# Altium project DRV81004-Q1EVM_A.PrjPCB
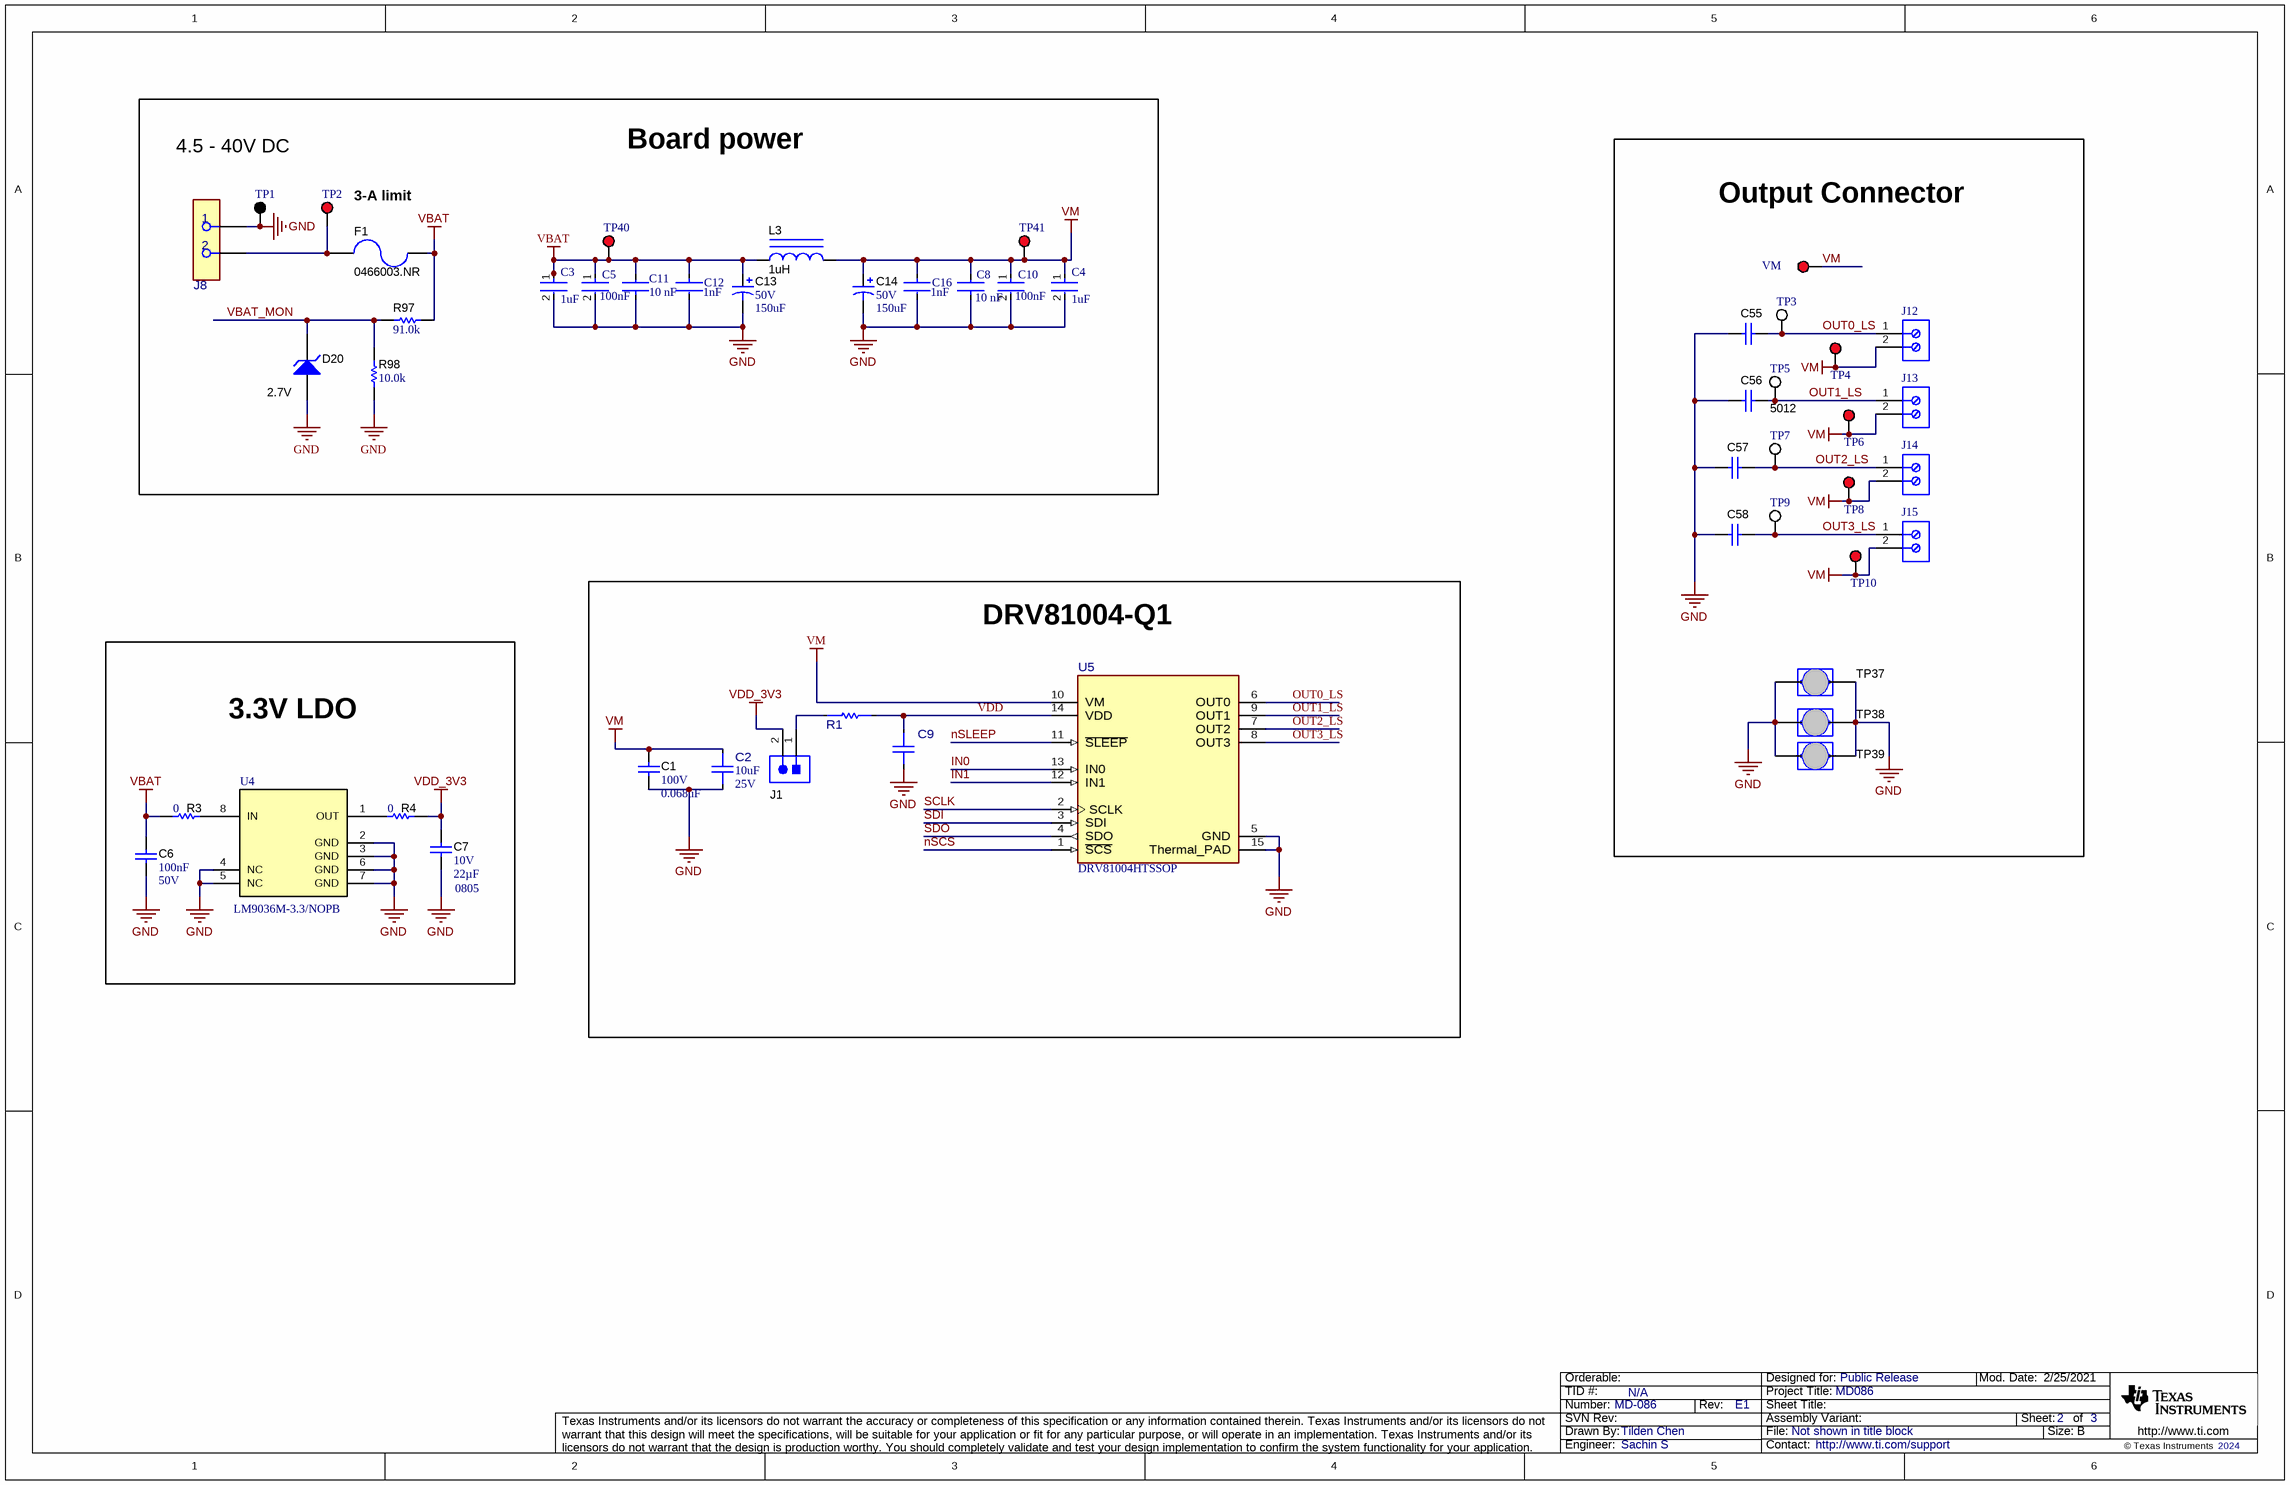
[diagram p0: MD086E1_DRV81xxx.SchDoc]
CopyrightYear: 2024; PCB_Layout: Audrey Kuehler; PCB_Rev: E1; PRJ_Customer: Public Release; PRJ_Engineer: Sachin S; PRJ_Number: MD-086; PRJ_Title: MD086; SCH_Rev: E1; TechSupport: http://www.ti.com/support; TID: N/A
4 sheets, 226 parts. Net scope: global (net labels, ports and power ports of the same name join across sheets).
Board file: DRV81004-Q1EVM_A -051324.PcbDoc
Sheets:
  MD086E1_DRV81xxx.SchDoc
  MD086E1_ezFET.SchDoc
  MD086E1_Hardware.SchDoc
  MD086E1_MCU.SchDoc

## Sheet MD086E1_DRV81xxx.SchDoc
size 431 x 279 mm; Date: Not shown in title block; ApprovedBy: Not shown in title block; CheckedBy: Not shown in title block; Author: Not shown in title block; CompanyName: Not shown in title block; DrawnBy: Tilden Chen; Engineer: Sachin S; Organization: Not shown in title block; Address1: Not shown in title block; Address2: Not shown in title block; Address3: Not shown in title block; Address4: Not shown in title block; DocumentNumber: 2; Revision: Use project parameter SCH_Rev; SheetNumber: 2; SheetTotal: 3; PageSetup: Record=PageOptions¦CenterHorizontal=True¦CenterVertical=True¦PrintScale=1.00¦XCorrection=1.00¦YCorrection=1.00¦PrintKind=0¦BorderSize=5000000¦LeftOffset=0¦BottomOffset=0¦Orientation=2¦PaperLength=1000¦PaperWidth=1000¦Scale=100¦PaperSource=15¦PrintQuality=600¦MediaType=1¦DitherType=10¦PaperKind=Letter¦PrintScaleMode=1

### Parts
C1  VDC_V: 100V  ValueDisplayed: 0.068uF  [1206]  (hidden comment: 12061C683KAT2A)
C2  ValueDisplayed: 10uF  VDC_V: 25V  [FP-ZRB18AR61E106ME01L_0603-MFG]  (hidden comment: ZRB18AR61E106ME01L)
C3  Capacitance: 1uF  [FP-0603-L_1_6_0_15-W_0_8-IPC_C]  (hidden comment: UMK107AB7105KA-T)
C4  Capacitance: 1uF  [FP-0603-L_1_6_0_15-W_0_8-IPC_C]  (hidden comment: UMK107AB7105KA-T)
C5  value 100nF  [FP-885012206095-MFG]  (hidden comment: 885012206095)
C6  Cap_F: 100nF  VDC_V: 50V  [0603]  (hidden comment: 885012206095)
C7  PackageReference: 0805  VDC_V: 10V  ValueDisplayed: 22µF  [0805_150]  (hidden comment: 885012107011)
C8  value 10 nF  [FP-CC0603-DA-MFG]  (hidden comment: CC0603KPX7R9BB103)
C9  885012205018  [FP-885012205018_0402-MFG]  (value not drawn)
C10  value 100nF  [FP-885012206095-MFG]  (hidden comment: 885012206095)
C11  value 10 nF  [FP-CC0603-DA-MFG]  (hidden comment: CC0603KPX7R9BB103)
C12  1nF  [FP-C0603C-CF-MFG]
C13  VDC_V: 50V  ValueDisplayed: 150uF  [SM_RADIAL_G]  (hidden comment: EEE-FK1H151P)
C14  VDC_V: 50V  ValueDisplayed: 150uF  [SM_RADIAL_G]  (hidden comment: EEE-FK1H151P)
C16  1nF  [FP-C0603C-CF-MFG]
C55  885012206114  [0603]  (value not drawn)
C56  885012206114  [0603]  (value not drawn)
C57  885012206114  [0603]  (value not drawn)
C58  885012206114  [0603]  (value not drawn)
D20  value 2.7V  [SOD-123]  (hidden comment: MMSZ4682-E3-08)
F1  0466003.NR  [1206]
J1  HTSW-102-07-G-S  [Samtec_HTSW-102-07-G-S]  (value not drawn)
J8  691250610002  [FP-691250610002_CONN_TERM_BLOCK2-MFG]  (value not drawn)
J12  691101710002  [691101710002]  (value not drawn)
J13  691101710002  [691101710002]  (value not drawn)
J14  691101710002  [691101710002]  (value not drawn)
J15  691101710002  [691101710002]  (value not drawn)
L3  ValueDisplayed: 1uH  [WE-HCC_1210]  (hidden comment: 7443320100)
R1  SG73S1JTTD101J  [FP-SG73S1JTTD101J_0603-MFG]  (value not drawn)
R3  value 0  [0603L]  (hidden comment: Resistor)
R4  value 0  [0603L]  (hidden comment: Resistor)
R97  ValueDisplayed: 91.0k  [0603L]  (hidden comment: RG1608P-913-B-T5)
R98  ValueDisplayed: 10.0k  [0603L]  (hidden comment: RG1608P-103-B-T5)
TP1  5011  [Keystone5011]  (value not drawn)
TP2  5010  [Keystone5010]  (value not drawn)
TP3  5012  [Keystone5012]  (value not drawn)
TP4  5010  [Keystone5010]  (value not drawn)
TP5  5012  [Keystone5012]
TP6  5010  [Keystone5010]  (value not drawn)
TP7  5012  [Keystone5012]  (value not drawn)
TP8  5010  [Keystone5010]  (value not drawn)
TP9  5012  [Keystone5012]  (value not drawn)
TP10  5010  [Keystone5010]  (value not drawn)
TP37  Jumper_2p  [Harwin_D3082-05]  (value not drawn)
TP38  Jumper_2p  [Harwin_D3082-05]  (value not drawn)
TP39  Jumper_2p  [Harwin_D3082-05]  (value not drawn)
TP40  5010  [Keystone5010]  (value not drawn)
TP41  5010  [Keystone5010]  (value not drawn)
U4  LM9036M-3.3/NOPB  [D0008A_N]
U5  DRV81004HTSSOP  [PWP0014L-MFG]
VM  5010  [Keystone5010]  (value not drawn)

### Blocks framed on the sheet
Board power: C3-C5 C8 C10-C14 C16 D20 F1 J8 L3 R97 R98 TP1 TP2 TP40 TP41
Output Connector: C55-C58 J12-J15 TP3-TP10 TP37-TP39 VM
DRV81004-Q1: C1 C2 C9 J1 R1 U5
3.3V LDO: C6 C7 R3 R4 U4

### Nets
GND: C1.2 C2.2 C3.2 C4.2 C5.2 C6.2 C7.2 C8.1 C9.2 C10.2 C11.1 C12.2 C13.2(-) C14.2(-) C16.2 C55.2 C56.2 C57.2 C58.2 D20.2(A) J8.1 R98.1 TP1.1 TP37.1 TP37.2 TP38.1 TP38.2 TP39.1 TP39.2 U4.2(GND) U4.3(GND) U4.4(NC) U4.5(NC) U4.6(GND) U4.7(GND) U5.5(GND) U5.15(Thermal_PAD)
VBAT: C3.1 C5.1 C6.1 C11.2 C12.1 C13.1(+) F1.1 L3.1 R3.2 R97.2 TP40.1  [project net VS]
VDD_3V3: C7.1 J1.2 R4.1
VM: C1.1 C2.1 C4.1 C8.2 C10.1 C14.1(+) C16.1 J12.2 J13.2 J14.2 J15.2 L3.2 TP4.1 TP6.1 TP8.1 TP10.1 TP41.1 U5.10(VM) VM.1
IN0: U5.13(IN0)
IN1: U5.12(IN1)
nSCS: U5.1(~{SCS})
nSLEEP: U5.11(~{SLEEP})
OUT0_LS: C55.1 J12.1 TP3.1 U5.6(OUT0)
OUT1_LS: C56.1 J13.1 TP5.1 U5.9(OUT1)
OUT2_LS: C57.1 J14.1 TP7.1 U5.7(OUT2)
OUT3_LS: C58.1 J15.1 TP9.1 U5.8(OUT3)
SCLK: U5.2(SCLK)
SDI: U5.3(SDI)
SDO: U5.4(SDO)
VBAT_MON: D20.1(K) R97.1 R98.2
VDD: C9.1 R1.2 U5.14(VDD)
NetF1_2: F1.2 J8.2 TP2.1
NetJ1_1: J1.1 R1.1
NetR3_1: R3.1 U4.8(IN)
NetR4_2: R4.2 U4.1(OUT)

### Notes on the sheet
- 4.5 - 40V DC
- 3-A limit

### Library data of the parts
C1 = CMP-0008507-2: CAP, CERM, 0.068 uF, 100 V, +/- 10%, X7R, 1206; Manufacturer: AVX; TaMin_C: -55°C; ESR_ohm: 0.045; Polarized: N; SizeAreaWB_mm2: 10.92; Value1: 0.045 ohm; U/M: EA; TaMax_C: 125°C; SizeZ_mm: 1.35; SizeX_mm: 3.2; SizeY_mm: 1.6; SizeArea_mm2: 5.12; Cap_F: 68nF; AEC Category: Q200
C2 = CMP-0094458-1: 10µF ±20% 25V Ceramic Capacitor X5R 0603 (1608 Metric); Manufacturer: Murata Electronics; SizeZ_mm: 1.2mm; AEC Qualified: No
C3 C4 = CMP-2000-07531-4: Ceramic Capacitor General Use 1uF ±10% 50V X7R 0603
C5 C10 = CMP-207839-000004-1: CAP CER 0.1UF 50V X7R 0603; Tolerance: 10%
C6 = CMP-0006837-4: CAP, CERM, 0.1 uF, 50 V, +/- 10%, X7R, 0603; Manufacturer: Wurth Elektronik; TaMin_C: -55°C; Polarized: N; SizeAreaWB_mm2: 4.68; Value1: Unknown; U/M: EA; Value: 0.1uF; TaMax_C: 125°C; SizeZ_mm: 1; SizeX_mm: 1.6; SizeY_mm: 0.8; SizeArea_mm2: 1.28; AEC Category: Q200
C7 = CMP-0078153-1: CAP, CERM, 22 µF, 10 V,+/- 20%, X5R, 0805; Manufacturer: Wurth Elektronik; TaMin_C: -55°C; Polarized: N; SizeAreaWB_mm2: 6.75; U/M: EA; Value: 22uF; TaMax_C: 85°C; SizeZ_mm: 1.5; SizeX_mm: 2; SizeY_mm: 1.25; SizeArea_mm2: 2.5; AEC Category: Q200
C8 C11 = CMP-1035-02321-3: CAP CER 10000PF 50V X7R 0603; Manufacturer: YAGEO; Alternative PartNumber: 885382206002; Alternative Manufacturer: Wurth Elektronik; Tolerance: 0.1; Material: Ceramic; Temperature Coefficient: 15%
C9 = CMP-0090362-1: 0.1µF ±10% 10V Ceramic Capacitor X7R 0402 (1005 Metric); Manufacturer: Wurth Electronics; AEC Qualified: No; Value: 100nF; SizeZ_mm: 0.55mm; ValueDisplayed: 100000pF; TempCo: 15%
C12 C16 = CMP-03020-030804-1: CAP CER 1000PF 50V X7R 0603; Manufacturer Part Number: C0603C102J5RACAUTO; Manufacturer: KEMET; Alternate PartNumber: 885012206083; Alternate Manufacturer: Wurth Elektronik; Material: Ceramic; Value: 1,000 pF; Temperature Coefficient: 30ppm/°C; Automotive Grade: Grade 1; Tolerance: 0.05
C13 C14 = CMP-0011178-2: CAP, AL, 150 uF, 50 V, +/- 20%, 0.18 ohm, AEC-Q200 Grade 2, SMD; Manufacturer: Panasonic; Alternate Manufacturer: Wurth Elektronik; Alternate PartNumber: 865080657017; TaMin_C: -55°C; ESR_ohm: 0.18; Polarized: Y; SizeAreaWB_mm2: 172.2; U/M: EA; Value: 150uF; TaMax_C: 105°C; SizeZ_mm: 10.2; SizeX_mm: 12; SizeY_mm: 10.3; Cap_Case: G; SizeArea_mm2: 123.6; CompType: Capacitor; Cap_F: 150µF; IRMS_A: 670mA; AEC Grade: 2; AEC Category: Q200
C55-C58 = CMP-0079993-1: CAP, CERM, 0.01 µF, 100 V,+/- 10%, X7R, 0603; Manufacturer: Wurth Elektronik; TaMin_C: -55°C; Polarized: N; SizeAreaWB_mm2: 4.68; U/M: EA; Value: 0.01uF; TaMax_C: 105°C; SizeZ_mm: 1; SizeX_mm: 1.6; SizeY_mm: 0.8; Value2: 100V; SizeArea_mm2: 1.28; Cap_F: 10nF; AEC Category: Q200; ValueDisplayed: 0.01µF
D20 = CMP-0077592-3: Diode, Zener, 2.7 V, 500 mW, SOD-123; Manufacturer: Vishay-Semiconductor; AEC Category: Q101; AEC Qualified: N; SizeAreaWB_mm2: 13.095; SizeY_mm: 1.7; SizeX_mm: 3.85; Value1: 0.5W; SizeArea_mm2: 6.545; SizeZ_mm: 1.35; RJA_CperW: 340; Power_W: 500mW
F1 = CMP-0084439-1: Fuse, 3 A, 32VAC/VDC, SMD; Manufacturer: Littelfuse; VAC_V: 32V; Rtyp_Ohm: 0.019; Interrupt_AC: 50A; MeltingTyp: 0.576; SizeX_mm: 3.2; Fuse Technology: Board Mount; Irating_A: 3A; SizeAreaWB_mm2: 10.92; TaMin_C: -55°C; Fuse Speed: Fast; SizeArea_mm2: 5.12; SizeY_mm: 1.6; SizeZ_mm: 1.35; TaMax_C: 90°C
J1 = CMP-0075483-1: Header, 100mil, 2x1, Gold, TH; Manufacturer: Samtec; Green_REACh: Passed; CT: False; Green_Lifecycle: Active; CNHeader: True
J8 = CMP-0093233-2: 2 Position Wire to Board Terminal Block Horizontal with Board 0.250" (6.35mm) Through Hole; Manufacturer: Wurth Electronics; Current_A: 32A; Conn Gender: Female; Row_Count: 1; ContactFinish: Zinc; SizeZ_mm: 21.6mm; Max Wire Gauge: 10; Min Wire Gauge: 30; Voltage_V: 450V; AEC Qualified: No; Is Female: yes
J12-J15 = CMP-1502-03256-1: Series 101 - 5.00 mm Horizontal Entry Modular with Pressure Clamp WR-TBL, 2 pin; Manufacturer: Wurth Elektronik; Pin Number: 2; Pitch: 5.00mm
L3 = CMP-0063986-1: Inductor, Shielded Drum Core, Ferrite, 1 uH, 24 A, 0.0012 ohm, SMD; Manufacturer: Wurth Elektronik; Isat: 32A @ 30% inductance drop; Irms: 24A @ 50C rise; Green_Lifecycle: Active; SizeAreaWB_mm2: 188.94; DCR_ohm: 1.2m; Green_REACh: Passed; Value: 1uH; Imax_A: 24A; SizeZ_mm: 10; SizeX_mm: 12.1; SizeY_mm: 11.4; SizeArea_mm2: 137.94; Ind_H: 1µH; AEC Category: Q200
R1 = CMP-0095262-1: 100 Ohms ±5% 0.2W, 1/5W Chip Resistor 0603 (1608 Metric) Automotive AEC-Q200, Moisture Resistant, Pulse Withstanding Thick Film; Manufacturer: KOA Speer; AEC Qualified: Yes; Value: 100; AEC Grade: Grade 0; VDC_V: 150V; TaMax_C: +70°C; TempCo: 100ppm/°C; Power_W: 200mW; SizeZ_mm: 0.55mm
R3 R4 = CMP-0025697-4: RES, 0, 5%, 0.1 W, AEC-Q200 Grade 0, 0603; PartNumber: CRCW06030000Z0EA; Manufacturer: Vishay-Dale; Value_Code: 0000; Power_W: 100mW; Value2: 0.1W; VDC_V: 75V; TempCo: 200 ppm/C; EIA_Code: E24; AEC Category: Q200; AEC Qualified: Y; SizeArea_mm2: 1.28; SizeX_mm: 1.6; SizeY_mm: 0.8; SizeZ_mm: 1
R97 = CMP-0023620-3: RES, 91.0 k, 0.1%, 0.1 W, 0603; Manufacturer: Susumu Co Ltd; Power_W: 100mW; TempCo: 25 ppm/C; Value_Code: 91k0; U/M: EA; Value: 91.0k; Res_ohm: 91k; SizeX_mm: 1.6; SizeY_mm: 0.8; SizeZ_mm: 1; Value2: 0.1W; SizeArea_mm2: 1.28; VDC_V: 75V; AEC Category: Q200
R98 = CMP-0023404-3: RES, 10.0 k, 0.1%, 0.1 W, 0603; Manufacturer: Susumu Co Ltd; Power_W: 100mW; TempCo: 25 ppm/C; Value_Code: 10k0; U/M: EA; Value: 10.0k; EIA_Code: E192; Res_ohm: 10k; SizeX_mm: 1.6; SizeY_mm: 0.8; SizeZ_mm: 1; Value2: 0.1W; SizeArea_mm2: 1.28; VDC_V: 75V; AEC Category: Q200
TP1 = CMP-0055148-2: Test Point, Multipurpose, Black, TH; Manufacturer: Keystone Electronics; CNHeader: FALSE; Green_Lifecycle: Active; Green_REACh: Passed; ContactFinish: Silver; CT: TRUE
TP2 TP4 TP6 TP8 TP10 VM = CMP-0055147-2: Test Point, Multipurpose, Red, TH; Manufacturer: Keystone Electronics; CNHeader: FALSE; Green_Lifecycle: Active; Green_REACh: Passed; ContactFinish: Silver; CT: TRUE
TP3 TP5 TP7 TP9 = CMP-0055149-2: Test Point, Multipurpose, White, TH; Manufacturer: Keystone Electronics; ContactFinish: Silver; CT: TRUE; CNHeader: FALSE; Green_Lifecycle: Active; Green_REACh: Passed
TP37-TP39 = CMP-0075110-1: 1mm Uninsulated Shorting Plug, 10.16mm spacing, TH; Manufacturer: Harwin; PartNumber: D3082-05; CompType: Jumper Wire; CNHeader: False; Green_Lifecycle: Active; Green_REACh: Passed
TP40 TP41 = CMP-0055147-1: Test Point, Multipurpose, Red, TH; Manufacturer: Keystone; CNHeader: FALSE; Green_Lifecycle: Active; Green_REACh: Passed; ContactFinish: Silver; CT: TRUE
U4 = CMP-0070570-1: Ultra-Low Quiescent Current Voltage Regulator, 8-pin Narrow SOIC, Pb-Free; Manufacturer: Texas Instruments; PackageTopMarking: NSZXTT*LM903*6M-3; PowerWise: N; CompType: LDO IC
U5 = CMP-0120416-1: 4-channel Low-side Driver for Automotive Relay Control; Manufacturer: Texas Instruments; SizeZ_mm: 1.2mm; AEC Qualified: No; Max Supply Voltage: 40V; Min Supply Voltage: 3V; Number Of Outputs: 4; Standoff Height: 0.05mm; TaMax_C: +125°C; TaMin_C: -40°C; TJmax_C: +150°C

## Sheet MD086E1_ezFET.SchDoc
size 431 x 279 mm; Date: Not shown in title block; ApprovedBy: Not shown in title block; CheckedBy: Not shown in title block; Author: Not shown in title block; CompanyName: Not shown in title block; DrawnBy: Murugavel Raju; Engineer: Sachin S; Organization: Not shown in title block; Address1: Not shown in title block; Address2: Not shown in title block; Address3: Not shown in title block; Address4: Not shown in title block; DocumentNumber: 1; Revision: Use project parameter SCH_Rev; SheetNumber: 1; SheetTotal: 3; PageSetup: Record=PageOptions¦CenterHorizontal=True¦CenterVertical=True¦PrintScale=1.00¦XCorrection=1.00¦YCorrection=1.00¦PrintKind=0¦BorderSize=5000000¦LeftOffset=0¦BottomOffset=0¦Orientation=2¦PaperLength=1000¦PaperWidth=1000¦Scale=100¦PaperSource=15¦PrintQuality=600¦MediaType=1¦DitherType=10¦PaperKind=Letter¦PrintScaleMode=1
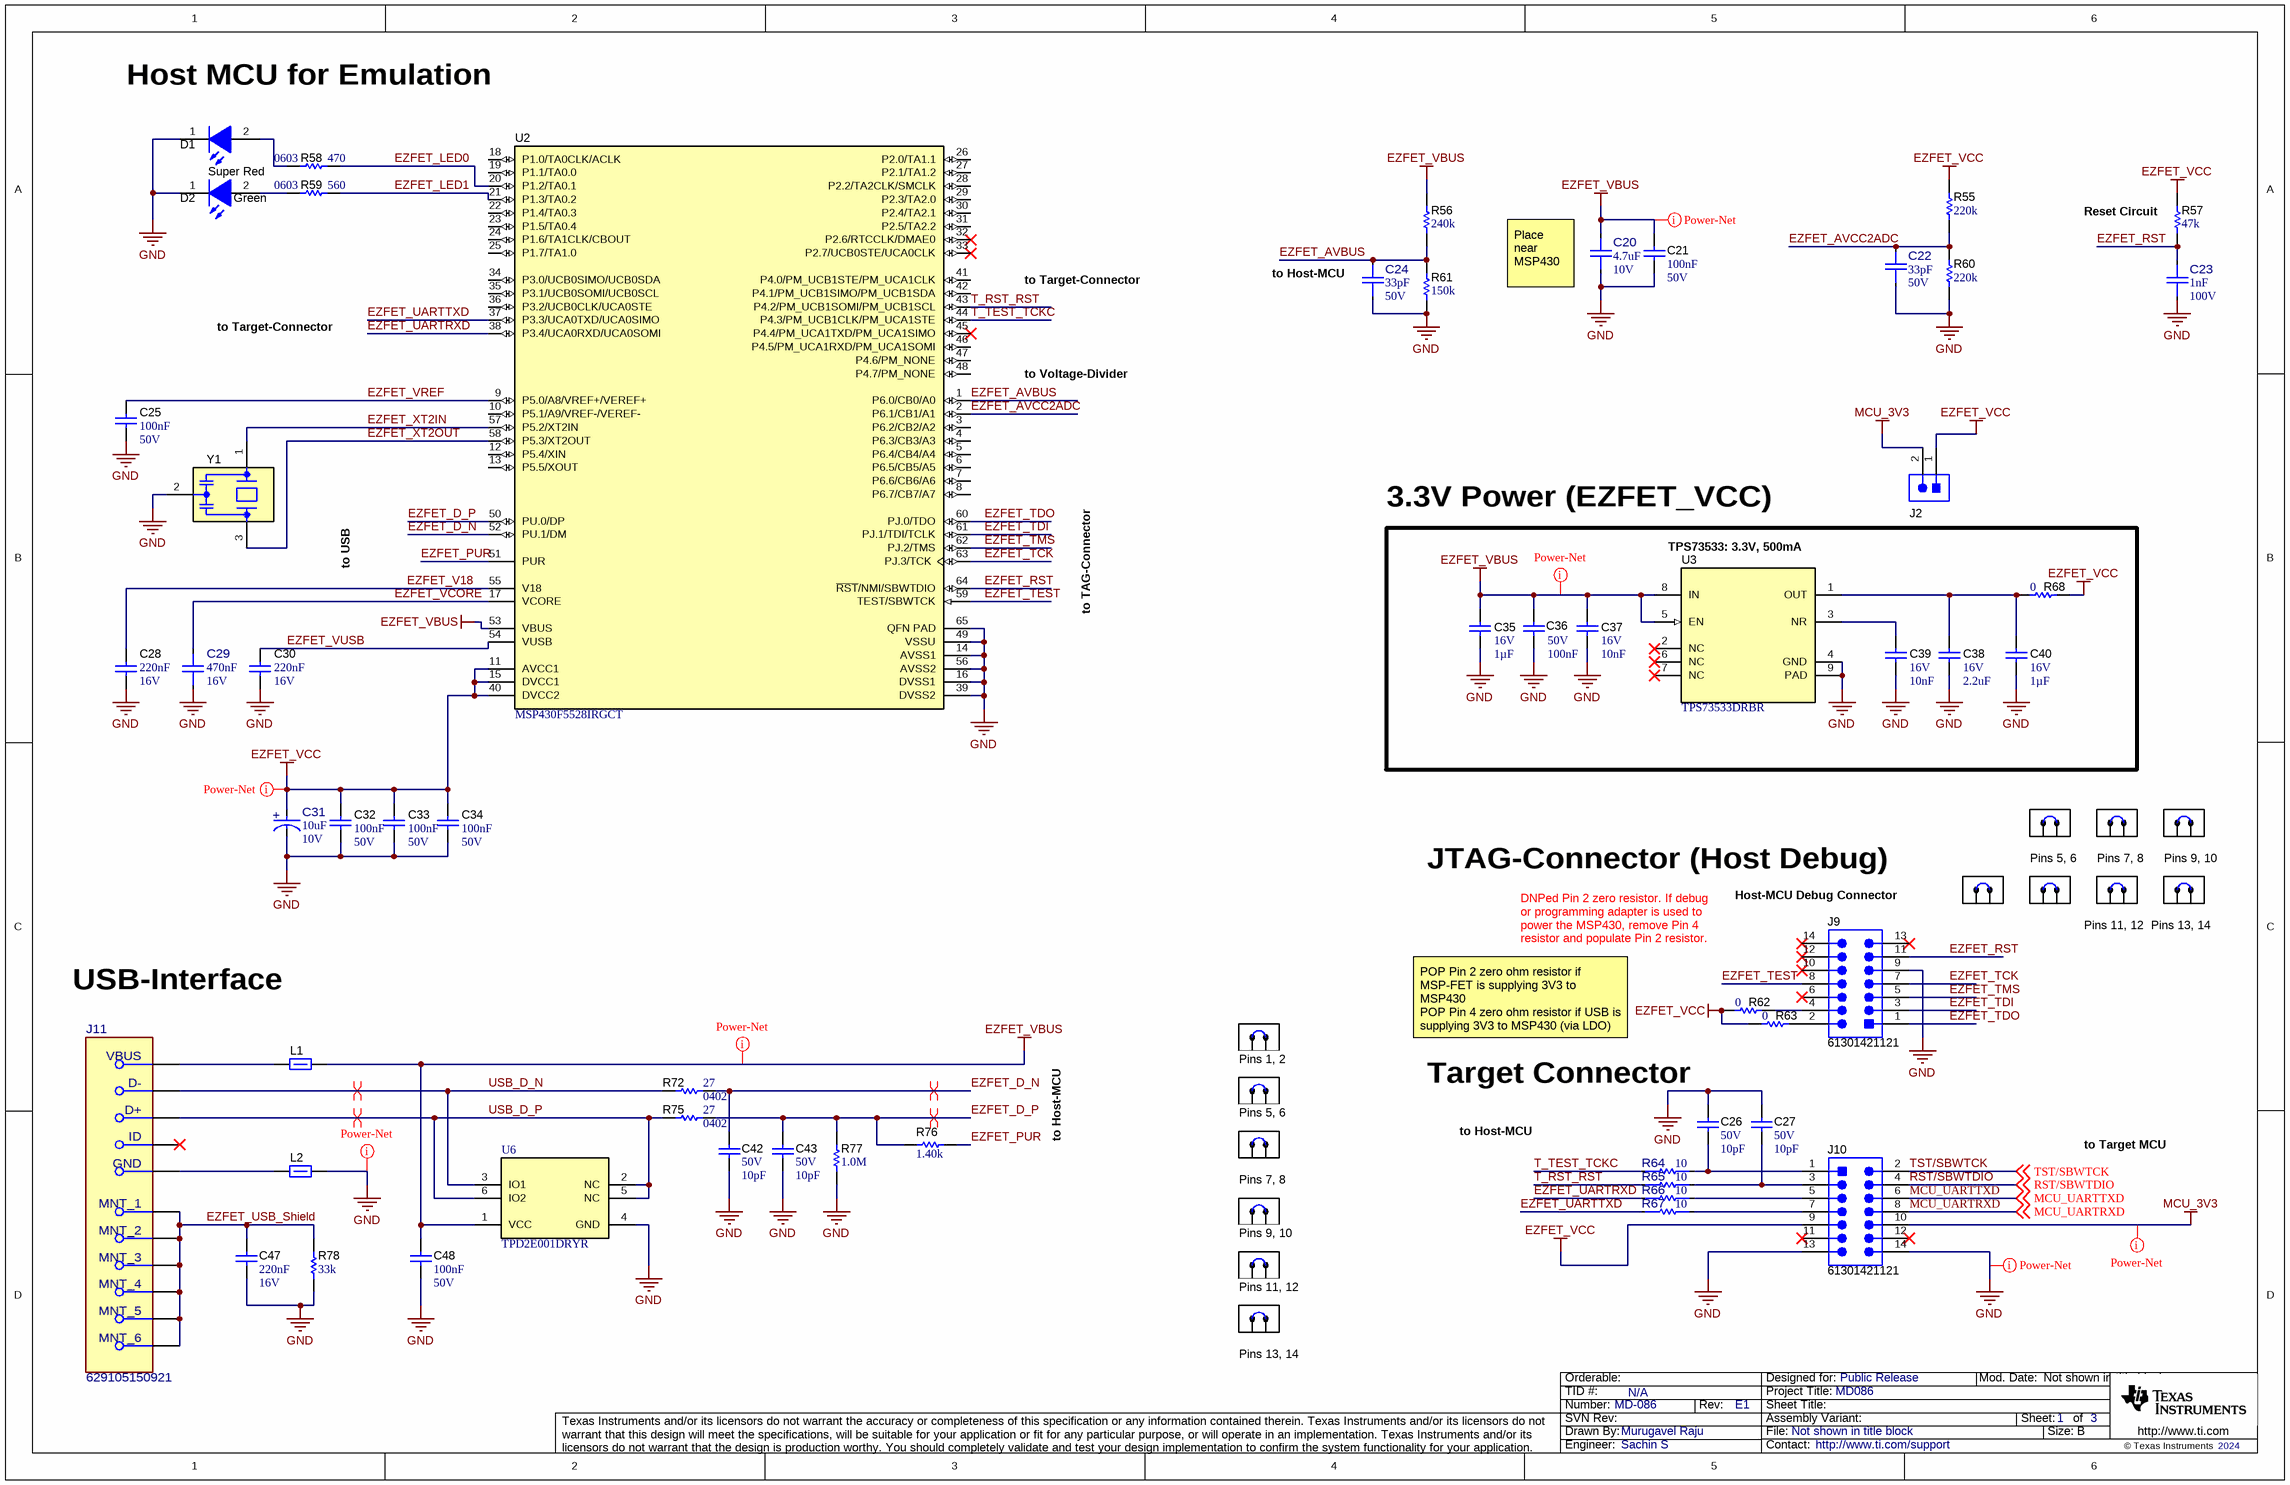
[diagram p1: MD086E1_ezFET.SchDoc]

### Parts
C20  ValueDisplayed: 4.7uF  VDC_V: 10V  [FP-885012106012_0603-MFG]  (hidden comment: 885012106012)
C21  Cap_F: 100nF  VDC_V: 50V  [0603]  (hidden comment: 885012206095)
C22  ValueDisplayed: 33pF  VDC_V: 50V  [FP-885012005058_0402-MFG]  (hidden comment: 885012005058)
C23  ValueDisplayed: 1nF  VDC_V: 100V  [FP-885012006085_0603-MFG]  (hidden comment: 885012006085)
C24  ValueDisplayed: 33pF  VDC_V: 50V  [FP-885012005058_0402-MFG]  (hidden comment: 885012005058)
C25  Cap_F: 100nF  VDC_V: 50V  [0603]  (hidden comment: 885012206095)
C26  VDC_V: 50V  ValueDisplayed: 10pF  [0402]  (hidden comment: 885012005055)
C27  VDC_V: 50V  ValueDisplayed: 10pF  [0402]  (hidden comment: 885012005055)
C28  Cap_F: 220nF  VDC_V: 16V  [0603L]  (hidden comment: 885012206048)
C29  VDC_V: 16V  Cap_F: 470nF  [FP-885012206050_0603-MFG]  (hidden comment: 885012206050)
C30  Cap_F: 220nF  VDC_V: 16V  [0603L]  (hidden comment: 885012206048)
C31  ValueDisplayed: 10uF  VDC_V: 10V  [FP-875105240001_SMT_CAP_4MM3_4MM3-MFG]  (hidden comment: 875105240001)
C32  Cap_F: 100nF  VDC_V: 50V  [0603]  (hidden comment: 885012206095)
C33  Cap_F: 100nF  VDC_V: 50V  [0603]  (hidden comment: 885012206095)
C34  Cap_F: 100nF  VDC_V: 50V  [0603]  (hidden comment: 885012206095)
C35  Cap_F: 1µF  VDC_V: 16V  [0603]  (hidden comment: 885012206052)
C36  Cap_F: 100nF  VDC_V: 50V  [0603]  (hidden comment: 885012206095)
C37  Cap_F: 10nF  VDC_V: 16V  [0603]  (hidden comment: 885012206040)
C38  VDC_V: 16V  ValueDisplayed: 2.2uF  [0603]  (hidden comment: 885012106018)
C39  Cap_F: 10nF  VDC_V: 16V  [0603]  (hidden comment: 885012206040)
C40  Cap_F: 1µF  VDC_V: 16V  [0603]  (hidden comment: 885012206052)
C42  VDC_V: 50V  ValueDisplayed: 10pF  [0402]  (hidden comment: 885012005055)
C43  VDC_V: 50V  ValueDisplayed: 10pF  [0402]  (hidden comment: 885012005055)
C47  Cap_F: 220nF  VDC_V: 16V  [0603L]  (hidden comment: 885012206048)
C48  Cap_F: 100nF  VDC_V: 50V  [0603]  (hidden comment: 885012206095)
D1  value Super Red  [WL-SMCW_RED]  (hidden comment: 150060SS75000)
D2  value Green  [WL-SMCW_GREEN]  (hidden comment: 150060VS75000)
J2  HTSW-102-07-G-S  [Samtec_HTSW-102-07-G-S]  (value not drawn)
J9  61301421121  [Wurth_61301421121]
J10  61301421121  [Wurth_61301421121]
J11  629105150921  [FP-629105150921_CONN_PTH_USB_8MM0_5MM6-MFG]
L1  742792621  [0603L]  (value not drawn)
L2  742792621  [0603L]  (value not drawn)
R55  ValueDisplayed: 220k  [0402]  (hidden comment: RC0402FR-07220KL)
R56  ValueDisplayed: 240k  [0402]  (hidden comment: CRCW0402240KFKED)
R57  ValueDisplayed: 47k  [0402]  (hidden comment: CRCW040247K0JNED)
R58  ValueDisplayed: 470  [0603]  (hidden comment: RC0603JR-07470RL)
R59  ValueDisplayed: 560  [0603]  (hidden comment: RC0603JR-07560RL)
R60  ValueDisplayed: 220k  [0402]  (hidden comment: RC0402FR-07220KL)
R61  ValueDisplayed: 150k  [0402]  (hidden comment: CRCW0402150KFKED)
R62  value 0  [0603L]  (hidden comment: Resistor)
R63  value 0  [0603L]  (hidden comment: Resistor)
R64  value 10  [FP-560050310009_0402-MFG]  (hidden comment: 560050310009)
R65  value 10  [FP-560050310009_0402-MFG]  (hidden comment: 560050310009)
R66  value 10  [FP-560050310009_0402-MFG]  (hidden comment: 560050310009)
R67  value 10  [FP-560050310009_0402-MFG]  (hidden comment: 560050310009)
R68  value 0  [0603L]  (hidden comment: Resistor)
R72  PackageReference: 0402  ValueDisplayed: 27  [0402L]  (hidden comment: CRCW040227R0JNED)
R75  PackageReference: 0402  ValueDisplayed: 27  [0402L]  (hidden comment: CRCW040227R0JNED)
R76  ValueDisplayed: 1.40k  [0402L]  (hidden comment: CRCW04021K40FKED)
R77  ValueDisplayed: 1.0M  [0402L]  (hidden comment: CRCW04021M00JNED)
R78  ValueDisplayed: 33k  [0402S]  (hidden comment: CRCW040233K0JNED)
SH-J22  60900213421  [Wurth_60900213421]  (value not drawn)
SH-J23  60900213421  [Wurth_60900213421]  (value not drawn)
SH-J24  60900213421  [Wurth_60900213421]  (value not drawn)
SH-J25  60900213421  [Wurth_60900213421]  (value not drawn)
SH-J26  60900213421  [Wurth_60900213421]  (value not drawn)
SH-J27  60900213421  [Wurth_60900213421]  (value not drawn)
SH-J28  60900213421  [Wurth_60900213421]  (value not drawn)
SH-J29  60900213421  [Wurth_60900213421]  (value not drawn)
SH-J31  60900213421  [Wurth_60900213421]  (value not drawn)
SH-J32  60900213421  [Wurth_60900213421]  (value not drawn)
SH-J33  60900213421  [Wurth_60900213421]  (value not drawn)
SH-J34  60900213421  [Wurth_60900213421]  (value not drawn)
SH-J35  60900213421  [Wurth_60900213421]  (value not drawn)
U2  MSP430F5528IRGCT  [RGC0064B]
U3  TPS73533DRBR  [DRB0008A]
U6  TPD2E001DRYR  [DRY0006A]
Y1  CSTNR4M00GH5L000R0  [MuRata_CSTNR]  (value not drawn)

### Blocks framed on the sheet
3.3V Power (EZFET_VCC): C35-C40 R68 U3

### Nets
EZFET_VBUS: C20.2 C21.1 C35.1 C36.1 C37.1 C48.2 L1.2 R56.2 U2.53(VBUS) U3.5(EN) U3.8(IN) U6.1(VCC)
EZFET_VCC: C31.2(ANODE) C32.1 C33.1 C34.1 J2.1 J10.9 R55.2 R57.2 R62.2 R63.2 R68.1 U2.11(AVCC1) U2.15(DVCC1) U2.40(DVCC2)
GND: C20.1 C21.2 C22.1 C23.1 C24.1 C25.2 C26.1 C27.1 C28.2 C29.1 C30.2 C31.1(CATHODE) C32.2 C33.2 C34.2 C35.2 C36.2 C37.2 C38.2 C39.2 C40.2 C42.2 C43.2 C47.2 C48.1 D1.1(K) D2.1(K) J9.9 J10.13 J10.14 L2.2 R60.1 R61.1 R77.1 R78.1 U2.14(AVSS1) U2.16(DVSS1) U2.39(DVSS2) U2.49(VSSU) U2.56(AVSS2) U2.65(QFN_PAD) U3.4(GND) U3.9(PAD) U6.4(GND) Y1.2(GND)
MCU_3V3: J2.2 J10.10
EZFET_AVBUS: C24.2 R56.1 R61.2 U2.1(P6.0/CB0/A0)
EZFET_AVCC2ADC: C22.2 R55.1 R60.2 U2.2(P6.1/CB1/A1)
EZFET_D_N: C42.1 R72.2 U2.52(PU.1/DM)
EZFET_D_P: C43.1 R75.2 R76.1 R77.2 U2.50(PU.0/DP)
EZFET_LED0: R58.1 U2.20(P1.2/TA0.1)
EZFET_LED1: R59.1 U2.21(P1.3/TA0.2)
EZFET_PUR: R76.2 U2.51(PUR)
EZFET_RST: C23.2 J9.11 R57.1 U2.64(~{RST}/NMI/SBWTDIO)
EZFET_TCK: J9.7 U2.63(PJ.3/TCK)
EZFET_TDI: J9.3 U2.61(PJ.1/TDI/TCLK)
EZFET_TDO: J9.1 U2.60(PJ.0/TDO)
EZFET_TEST: J9.8 U2.59(TEST/SBWTCK)
EZFET_TMS: J9.5 U2.62(PJ.2/TMS)
EZFET_UARTRXD: R66.1 U2.38(P3.4/UCA0RXD/UCA0SOMI)
EZFET_UARTTXD: R67.1 U2.37(P3.3/UCA0TXD/UCA0SIMO)
EZFET_USB_Shield: C47.1 J11.6(MNT_1) J11.7(MNT_2) J11.8(MNT_3) J11.9(MNT_4) J11.10(MNT_5) J11.11(MNT_6) R78.2
EZFET_V18: C28.1 U2.55(V18)
EZFET_VCORE: C29.2 U2.17(VCORE)
EZFET_VREF: C25.1 U2.9(P5.0/A8/VREF+/VEREF+)
EZFET_VUSB: C30.1 U2.54(VUSB)
EZFET_XT2IN: U2.57(P5.2/XT2IN) Y1.1(In)
EZFET_XT2OUT: U2.58(P5.3/XT2OUT) Y1.3(Out)
MCU_UARTRXD: J10.8 ; off-sheet MCU_UARTRXD
MCU_UARTTXD: J10.6 ; off-sheet MCU_UARTTXD
RST/SBWTDIO: J10.4 ; off-sheet RST/SBWTDIO
T_RST_RST: R65.1 U2.43(P4.2/PM_UCB1SOMI/PM_UCB1SCL)
T_TEST_TCKC: R64.1 U2.44(P4.3/PM_UCB1CLK/PM_UCA1STE)
TST/SBWTCK: J10.2 ; off-sheet TST/SBWTCK
USB_D_N: J11.2(D-) R72.1 U6.3(IO1)
USB_D_P: J11.3(D+) R75.1 U6.2(NC) U6.5(NC) U6.6(IO2)
NetC26_2: C26.2 J10.1 R64.2
NetC27_2: C27.2 J10.3 R65.2
NetC38_1: C38.1 C40.1 R68.2 U3.1(OUT)
NetC39_1: C39.1 U3.3(NR)
NetD1_2: D1.2(A) R58.2
NetD2_2: D2.2(A) R59.2
NetJ9_2: J9.2 R63.1
NetJ9_4: J9.4 R62.1
NetJ10_5: J10.5 R66.2
NetJ10_7: J10.7 R67.2
NetJ11_1: J11.1(VBUS) L1.1
NetJ11_5: J11.5(GND) L2.1

Not connected (* = marked no-connect by the designer): J9 6* 10* 12* 13* 14*; J10 11* 12*; J11 4(ID)*; U2 3(P6.2/CB2/A2) 4(P6.3/CB3/A3) 5(P6.4/CB4/A4) 6(P6.5/CB5/A5) 7(P6.6/CB6/A6) 8(P6.7/CB7/A7) 10(P5.1/A9/VREF-/VEREF-) 12(P5.4/XIN) 13(P5.5/XOUT) 18(P1.0/TA0CLK/ACLK) 19(P1.1/TA0.0) 22(P1.4/TA0.3) 23(P1.5/TA0.4) 24(P1.6/TA1CLK/CBOUT) 25(P1.7/TA1.0) 26(P2.0/TA1.1) 27(P2.1/TA1.2) 28(P2.2/TA2CLK/SMCLK) 29(P2.3/TA2.0) 30(P2.4/TA2.1) 31(P2.5/TA2.2) 32(P2.6/RTCCLK/DMAE0)* 33(P2.7/UCB0STE/UCA0CLK)* 34(P3.0/UCB0SIMO/UCB0SDA) 35(P3.1/UCB0SOMI/UCB0SCL) 36(P3.2/UCB0CLK/UCA0STE) 41(P4.0/PM_UCB1STE/PM_UCA1CLK) 42(P4.1/PM_UCB1SIMO/PM_UCB1SDA) 45(P4.4/PM_UCA1TXD/PM_UCA1SIMO)* 46(P4.5/PM_UCA1RXD/PM_UCA1SOMI) 47(P4.6/PM_NONE) 48(P4.7/PM_NONE); U3 2(NC)* 6(NC)* 7(NC)*

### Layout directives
net class Power-Net: EZFET_VBUS, EZFET_VCC, GND, MCU_3V3
differential pair: EZFET_D_N, EZFET_D_P, USB_D_N, USB_D_P

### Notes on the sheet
- Host MCU for Emulation
- (near R57) Reset Circuit
- to Target-Connector
- (near C24) to Host-MCU
- (near C20) Place near MSP430
- to Voltage-Divider
- to USB
- to TAG-Connector
- (near U3) TPS73533: 3.3V, 500mA
- JTAG-Connector (Host Debug)
- (near J9) Host-MCU Debug Connector
- (near SH-J23) Pins 5, 6
- (near SH-J27) Pins 7, 8
- (near SH-J28) Pins 9, 10
- DNPed Pin 2 zero resistor. If debug or programming adapter is used to power the MSP430, remove Pin 4 resistor and populate Pin 2 resistor.
- Pins 11, 12
- Pins 13, 14
- USB-Interface
- POP Pin 2 zero ohm resistor if MSP-FET is supplying 3V3 to MSP430
  POP Pin 4 zero ohm resistor if USB is supplying 3V3 to MSP430 (via LDO)
- to Host-MCU
- (near SH-J29) Pins 1, 2
- Target Connector
- (near SH-J31) Pins 5, 6
- to Target MCU
- Pins 7, 8
- (near SH-J33) Pins 9, 10
- (near SH-J34) Pins 11, 12
- (near SH-J35) Pins 13, 14

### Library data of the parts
C20 = CMP-0097305-1: 4.7 µF ±20% 10V Ceramic Capacitor X5R 0603 (1608 Metric); Manufacturer: Wurth Electronics; Cap_F: 4.7µF; Value: 4.7µF; AEC Qualified: No; SizeZ_mm: 0.87mm; TempCo: 15%
C21 C25 C32-C34 C36 C48 = CMP-0006837-4: as C6 on sheet MD086E1_DRV81xxx
C22 C24 = CMP-0097306-1: 33 pF ±5% 50V Ceramic Capacitor C0G, NP0 0402 (1005 Metric); Manufacturer: Wurth Electronics; AEC Qualified: No; Value: 33pF; TempCo: 30ppm/°C; SizeZ_mm: 0.55mm
C23 = CMP-0097311-1: 1000 pF ±5% 100V Ceramic Capacitor C0G, NP0 0603 (1608 Metric); Manufacturer: Wurth Electronics; TempCo: 30ppm/°C; SizeZ_mm: 0.87mm; AEC Qualified: No; Value: 1nF
C26 C27 C42 C43 = CMP-0006215-2: CAP, CERM, 10 pF, 50 V, +/- 5%, C0G/NP0, 0402; Manufacturer: Wurth Elektronik; TaMin_C: -55°C; Polarized: N; SizeAreaWB_mm2: 3; Value1: Unknown; U/M: EA; Value: 10pF; TaMax_C: 125°C; SizeZ_mm: 0.6; SizeX_mm: 1; SizeY_mm: 0.5; AEC Category: Q200
C28 C30 C47 = CMP-0006830-4: CAP, CERM, 0.22 uF, 16 V, +/- 10%, X7R, 0603; Manufacturer: Wurth Elektronik; TaMin_C: -55°C; Polarized: N; SizeAreaWB_mm2: 4.68; Value1: Unknown; U/M: EA; Value: 0.22uF; TaMax_C: 125°C; SizeZ_mm: 1; SizeX_mm: 1.6; SizeY_mm: 0.8; Cap_Case: 0603; SizeArea_mm2: 1.28; AEC Category: Q200
C29 = CMP-0097608-1: 0.47 µF ±10% 16V Ceramic Capacitor X7R 0603 (1608 Metric); Manufacturer: Wurth Electronics; AEC Qualified: No; Value: 470nF; TempCo: 15%; SizeZ_mm: 0.87mm
C31 = CMP-0097340-1: Alum. Polymer Cap 10µF 10V 5.5mmV-Chip WCAP-PSLP Series Lifetime 2000h +105°C; Manufacturer: Wurth Electronics; Life: 2000Hours; Dissipation Factor: 8%; Esr: 45m; IRMS_A: 1.2A; Tolerance_%: 20%; AEC Qualified: No; SizeZ_mm: 5.5mm; Leakage Current: 300uA
C35 C40 = CMP-0006831-4: CAP, CERM, 1 uF, 16 V, +/- 10%, X7R, 0603; Manufacturer: Wurth Elektronik; TaMin_C: -55°C; Polarized: N; SizeAreaWB_mm2: 4.68; Value1: Unknown; U/M: EA; Value: 1uF; TaMax_C: 125°C; SizeZ_mm: 1; SizeX_mm: 1.6; SizeY_mm: 0.8; SizeArea_mm2: 1.28; AEC Category: Q200
C37 C39 = CMP-0006828-4: CAP, CERM, 0.01 uF, 16 V, +/- 10%, X7R, 0603; Manufacturer: Wurth Elektronik; TaMin_C: -55°C; Polarized: N; SizeAreaWB_mm2: 4.68; Value1: Unknown; U/M: EA; Value: 0.01uF; TaMax_C: 125°C; SizeZ_mm: 1; SizeX_mm: 1.6; SizeY_mm: 0.8; SizeArea_mm2: 1.28; AEC Category: Q200
C38 = CMP-0006825-5: CAP, CERM, 2.2 uF, 16 V, +/- 20%, X5R, 0603; Manufacturer: Wurth Elektronik; TaMin_C: -55°C; Polarized: N; SizeAreaWB_mm2: 4.68; Value1: Unknown; U/M: EA; Value: 2.2uF; TaMax_C: 85°C; SizeZ_mm: 1; SizeX_mm: 1.6; SizeY_mm: 0.8; SizeArea_mm2: 1.28; Cap_F: 2.2µF; AEC Category: Q200
D1 = CMP-0002893-1: LED, Super Red, SMD; Manufacturer: Wurth Elektronik; Io_A: 20mA; Value1: W; U/M: EA; Vf_V: 1.9V; Type: AlInGaP
D2 = CMP-0002894-2: LED, Green, SMD; Manufacturer: Wurth Elektronik; Type: AlInGaP; Vf_V: 2V; Io_A: 20mA; Value1: W
J2 = CMP-0075483-1: as J1 on sheet MD086E1_DRV81xxx
J9 J10 = CMP-0086014-1: Header, 2.54mm, 7x2, Gold, TH; Manufacturer: Wurth Elektronik; Pitch_mm: 2.54; Voltage_V: 250V; Shrouded: N; Gender: Male; Current_A: 3A; Cert_UL: Y; Row_Count: 2
J11 = CMP-0097752-1: Conn Micro USB 2.0 Type AB RCP 5 POS 0.65mm Solder RA SMD 5 Terminal 1 Port T/R; Manufacturer: Wurth Electronics; Shrouded: true; Voltage_V: 30V; Usb Standard: USB 2.0; Current_A: 1A; ContactFinish: Gold; SizeZ_mm: 3.2mm; Is Female: yes; Conn Orientation: Horizontal; AEC Qualified: No
L1 L2 = CMP-0003184-2: Ferrite Bead, 140 ohm @ 100 MHz, 0.55 A, 0603; Manufacturer: Wurth Elektronik; Ztyp@1GHz_Ohm: 271.401; ZTyp@100MHz_Ohm: 140; SizeAreaWB_mm2: 4.68; DCR_ohm: 0.2; Value1: 0.2 ohm; Value: 140 ohm; Imax_A: 550mA; SizeZ_mm: 1; SizeX_mm: 1.6; SizeY_mm: 0.8; Value2: 0.55A; SizeArea_mm2: 1.28
R55 R60 = CMP-0026728-1: RES, 220 k, 1%, 0.0625 W, 0402; Manufacturer: Yageo America; Power_W: 62.5mW; TempCo: 100 ppm/C; U/M: EA; Value: 220k; SizeX_mm: 1; SizeY_mm: 0.5; SizeZ_mm: 0.6; AEC Qualified: N; VDC_V: 50V; AEC Category: Q200
R56 = CMP-0026190-2: RES, 240 k, 1%, 0.063 W, AEC-Q200 Grade 0, 0402; Manufacturer: Vishay-Dale; Power_W: 63mW; TempCo: 100 ppm/C; Value: 240k; SizeX_mm: 1; SizeY_mm: 0.5; SizeZ_mm: 0.6; Value2: 0.063W; AEC Qualified: Y; VDC_V: 50V; AEC Category: Q200; AEC Grade: 0
R57 = CMP-0026935-3: RES, 47 k, 5%, 0.063 W, AEC-Q200 Grade 0, 0402; Manufacturer: Vishay-Dale; Power_W: 63mW; TempCo: 200 ppm/C; Value_Code: 47k0; Value: 47k; EIA_Code: E24; SizeX_mm: 1; SizeY_mm: 0.5; SizeZ_mm: 0.6; Value2: 0.063W; AEC Qualified: Y; VDC_V: 50V; AEC Category: Q200; AEC Grade: 0
R58 = CMP-0025924-5: RES, 470, 5%, 0.1 W, 0603; Manufacturer: Yageo; Power_W: 100mW; TempCo: 100 ppm/C; Value_Code: 470R; Value: 470; EIA_Code: E24; SizeX_mm: 1.6; SizeY_mm: 0.8; SizeZ_mm: 1; Value2: 0.1W; SizeArea_mm2: 1.28; AEC Qualified: N; VDC_V: 75V; AEC Category: Q200; SizeAreaWB_mm2: 4.68
R59 = CMP-0025930-5: RES, 560, 5%, 0.1 W, 0603; Manufacturer: Yageo; Power_W: 100mW; TempCo: 100 ppm/C; Value_Code: 560R; Value: 560; EIA_Code: E24; SizeX_mm: 1.6; SizeY_mm: 0.8; SizeZ_mm: 1; Value2: 0.1W; SizeArea_mm2: 1.28; AEC Qualified: N; VDC_V: 75V; AEC Category: Q200; SizeAreaWB_mm2: 4.68
R61 = CMP-0026021-3: RES, 150 k, 1%, 0.063 W, AEC-Q200 Grade 0, 0402; Manufacturer: Vishay-Dale; Power_W: 63mW; TempCo: 100 ppm/C; Value: 150k; EIA_Code: E96; SizeX_mm: 1; SizeY_mm: 0.5; SizeZ_mm: 0.6; Value2: 0.063W; AEC Qualified: Y; VDC_V: 50V; AEC Category: Q200; AEC Grade: 0
R62 R63 R68 = CMP-0025697-4: as R3 on sheet MD086E1_DRV81xxx
R64-R67 = CMP-0097401-1: Thick Film Resistors 0402 10Ω ±1% 0.125W; Manufacturer: Wurth Electronics; TempCo: 100ppm/°C; VDC_V: 1.118V; Power_W: 125mW; AEC Qualified: No; SizeZ_mm: 0.4mm
R72 R75 = CMP-0026888-3: RES, 27, 5%, 0.063 W, AEC-Q200 Grade 0, 0402; Manufacturer: Vishay-Dale; Power_W: 63mW; TempCo: 200 ppm/C; Value_Code: 27R0; Value: 27; EIA_Code: E24; SizeX_mm: 1; SizeY_mm: 0.5; SizeZ_mm: 0.6; Value2: 0.063W; AEC Qualified: Y; VDC_V: 50V; AEC Category: Q200; AEC Grade: 0
R76 = CMP-0026085-3: RES, 1.40 k, 1%, 0.063 W, AEC-Q200 Grade 0, 0402; Manufacturer: Vishay-Dale; Power_W: 63mW; TempCo: 100 ppm/C; Value_Code: 1k40; Value: 1.40k; EIA_Code: E96; Res_ohm: 1.4k; SizeX_mm: 1; SizeY_mm: 0.5; SizeZ_mm: 0.6; Value2: 0.063W; AEC Qualified: Y; VDC_V: 50V; AEC Category: Q200; AEC Grade: 0
R77 = CMP-0026859-2: RES, 1.0 M, 5%, 0.063 W, AEC-Q200 Grade 0, 0402; Manufacturer: Vishay-Dale; Power_W: 63mW; TempCo: 200 ppm/C; Value_Code: 1M00; Value: 1.0Meg; EIA_Code: E24; Res_ohm: 1M; SizeX_mm: 1; SizeY_mm: 0.5; SizeZ_mm: 0.6; Value2: 0.063W; AEC Qualified: Y; VDC_V: 50V; AEC Category: Q200; AEC Grade: 0
R78 = CMP-0026907-3: RES, 33 k, 5%, 0.063 W, AEC-Q200 Grade 0, 0402; Manufacturer: Vishay-Dale; Power_W: 63mW; TempCo: 200 ppm/C; Value_Code: 33k0; Value: 33k; EIA_Code: E24; SizeX_mm: 1; SizeY_mm: 0.5; SizeZ_mm: 0.6; Value2: 0.063W; AEC Qualified: Y; VDC_V: 50V; AEC Category: Q200; AEC Grade: 0
SH-J22-SH-J29 SH-J31-SH-J35 = CMP-0003761-2: Shunt, 2.54mm, Gold, Black; Manufacturer: Wurth Elektronik
U2 = CMP-0039269-4: 16-Bit Ultra-Low-Power Microcontroller, 128KB Flash, 8KB RAM, USB, 12Bit ADC, 2 USCIs, 32Bit HW MPY, RGC0064B (VQFN-64); Alternate Manufacturer: Texas Instruments; Alternate PartNumber: MSP430F5528IRGCR; ADC: 12-bit SAR; ADC Channels: 16; Brown Out Reset: Yes; DMA: 3; Flash(KB): 128; Frequency(MHz): 25; GPIO: 47; Multiplier: 32x32; SRAM(B): 8192; Timers - 16-bit: 4; USB: 1; USCI_A (UART/LIN/IrDA/SPI): 2; Rating: Catalog; SizeArea_mm2: 81.0; SizeZ_mm: 1.0; Green_REACh: Passed; AEC Qualified: N; AEC Category: Q200; CompType: IC; Green_Lifecycle: Active; SizeY_mm: 9.0; SizeAreaWB_mm2: 121.0
U3 = CMP-0036328-3: 500mA, Adjustable, Low Quiescent Current, Low-Noise, High-PSRR, Single-Output LDO Regulator, DRB0008A (VSON-8); Manufacturer: Texas Instruments; CompType: IC; Green_Lifecycle: Active; SizeZ_mm: 1.0; Iq(Typ)(mA): 0.04; SizeY_mm: 3.0; SizeAreaWB_mm2: 16.0; SizeArea_mm2: 9.0; AEC Category: Q200; Vout Adj(Max)(V): 3.3; AEC Qualified: N; Accuracy(%): 2; Vin(Max)(V): 6.5; Vdo(Typ)(mV): 280; Iout(Max)(A): 0.5; Green_REACh: Passed; Rating: Catalog; Vin(Min)(V): 2.7
U6 = CMP-0043099-3: Low-Capacitance 2-Channel +/-15kV ESD Protection Array for High-Speed Data Interfaces, DRY0006A (USON-6); Manufacturer: Texas Instruments; IO Leakage Current(nA): 1; IEC 61000-4-2 Air-Gap(+/- kV): 15; USB High Speed: TRUE; IO Capacitance(Typ)(pF): 1.5; Eco-Plan: Green (RoHS & no Sb/Br); Breakdown Voltage(Min)(V): 11; IEC 61000-4-2 Contact(+/- kV): 8; AEC Category: Q200; AEC Qualified: N; CompType: IC; SizeAreaWB_mm2: 4.9; SizeArea_mm2: 1.45; SizeX_mm: 1.0; SizeZ_mm: 0.6; Rating: Catalog
Y1 = CMP-0085483-1: Oscillator, 4 MHz, 700 ppm, 39 pF, SMD; Manufacturer: MuRata; SizeArea_mm2: 9; Load Capacitance: 39 pF; SizeZ_mm: 1.2; AEC Category: Q200; Frequency Tolerance: 700 ppm; SizeX_mm: 4.5; SizeAreaWB_mm2: 16.5; TaMax_C: 85°C; TaMin_C: -20°C; SizeY_mm: 2; AEC Qualified: N; Frequency_Fixed: 4MHz

## Sheet MD086E1_Hardware.SchDoc
size A
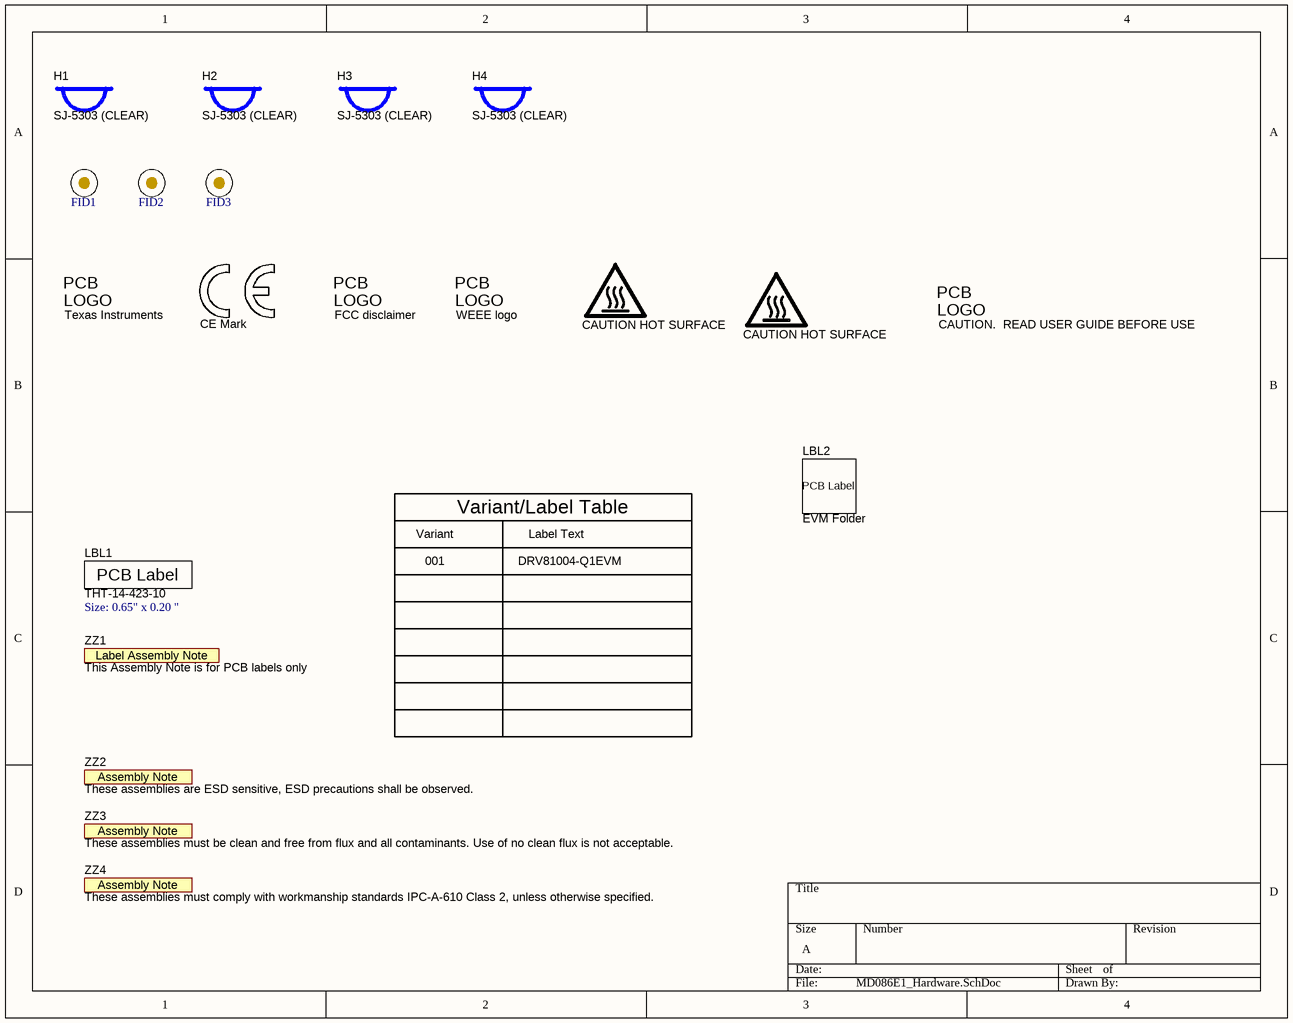
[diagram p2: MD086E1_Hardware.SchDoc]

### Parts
FID1  Fiducial  [Fiducial10-20]  (value not drawn)
FID2  Fiducial  [Fiducial10-20]  (value not drawn)
FID3  Fiducial  [Fiducial10-20]  (value not drawn)
H1  SJ-5303 (CLEAR)  [Bumpon_SJ5003Transparent]
H2  SJ-5303 (CLEAR)  [Bumpon_SJ5003Transparent]
H3  SJ-5303 (CLEAR)  [Bumpon_SJ5003Transparent]
H4  SJ-5303 (CLEAR)  [Bumpon_SJ5003Transparent]
LBL1  THT-14-423-10  Note: Size: 0.65" x 0.20 "  [Label_650x200]
LBL2  EVM Folder  [Label_375x375]
Logo1  CE Mark  [CE_Mark_5mm]  (no BOM)
Logo2  Texas Instruments  [TI_Stacked_Overlay_Small]  (no BOM)
Logo3  FCC disclaimer  [FCC_disclaimer]  (no BOM)
Logo4  WEEE logo  [WEEE_Minimum]  (no BOM)
Logo5  CAUTION.  READ USER GUIDE BEFORE USE  [IEC_Caution_Small]  (no BOM)
LOGO6  CAUTION HOT SURFACE  [IEC_HotSurface_Small]  (no BOM)
LOGO7  CAUTION HOT SURFACE  [IEC_HotSurface_Small]  (no BOM)
ZZ1  This Assembly Note is for PCB labels only  [AssemblyNoteLabel]  (no BOM)
ZZ2  These assemblies are ESD sensitive, ESD precautions shall be observed.  [AssemblyNote]  (no BOM)
ZZ3  These assemblies must be clean and free from flux and all contaminants. Use of no clean flux is not acceptable.  [AssemblyNote]  (no BOM)
ZZ4  These assemblies must comply with workmanship standards IPC-A-610 Class 2, unless otherwise specified.  [AssemblyNote]  (no BOM)

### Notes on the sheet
- Variant/Label Table
- Variant
- 001
- Label Text
- DRV81004-Q1EVM

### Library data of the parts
FID1-FID3 = CMP-0077181-1: Fiducial mark.  There is nothing to buy or mount.
H1-H4 = CMP-0003620-1: Bumpon, Hemisphere, 0.44 X 0.20, Clear; Manufacturer: 3M
LBL1 = CMP-0003625-1: Thermal Transfer Printable Labels, 0.650" W x 0.200" H - 10,000 per roll; Manufacturer: Brady
LBL2 = CMP-00007-1: Harsh Environment Multi-Purpose Polyester Labels for 3" Core Printers - 0.375" x 0.375", White; Manufacturer: Brady; PartNumber: THT-14-423-10; Body Material: PET,Polyester; Note: Size: 0.375" x 0.375"
Logo1 = CMP-0074844-1: SymbolCreator: a0412235
Logo2 = CMP-0074838-1: Texas Instrument Corporate Signature; SymbolCreator: a0412235; Lib Reference: TI_Logo
Logo3 = CMP-0074847-1: FCC_disclaimer
Logo4 = CMP-0074769-3: Manufacturer: Texas Instruments; CompType: IC; AEC Category: Q200
Logo5 = CMP-0074836-1: IEC 61010-1 Caution Warning; SymbolCreator: a0412235; Lib Reference: IEC_Caution
LOGO6 LOGO7 = CMP-0074837-2: IEC 61010-1 Hot Surface Warning; Manufacturer: Texas Instruments; SymbolCreator: a0412235; CompType: IC; AEC Category: Q200
ZZ1 = CMP-0003616-3
ZZ2 = CMP-0077236-1
ZZ3 = CMP-0077237-1
ZZ4 = CMP-0077238-1

## Sheet MD086E1_MCU.SchDoc
size 431 x 279 mm; Date: Not shown in title block; ApprovedBy: Not shown in title block; CheckedBy: Not shown in title block; Author: Not shown in title block; CompanyName: Not shown in title block; DrawnBy: Tilden Chen; Engineer: Sachin S; Organization: Not shown in title block; Address1: Not shown in title block; Address2: Not shown in title block; Address3: Not shown in title block; Address4: Not shown in title block; DocumentNumber: 2; Revision: Use project parameter SCH_Rev; SheetNumber: 2; SheetTotal: 3; PageSetup: Record=PageOptions¦CenterHorizontal=True¦CenterVertical=True¦PrintScale=1.00¦XCorrection=1.00¦YCorrection=1.00¦PrintKind=0¦BorderSize=5000000¦LeftOffset=0¦BottomOffset=0¦Orientation=2¦PaperLength=1000¦PaperWidth=1000¦Scale=100¦PaperSource=15¦PrintQuality=600¦MediaType=1¦DitherType=10¦PaperKind=Letter¦PrintScaleMode=1
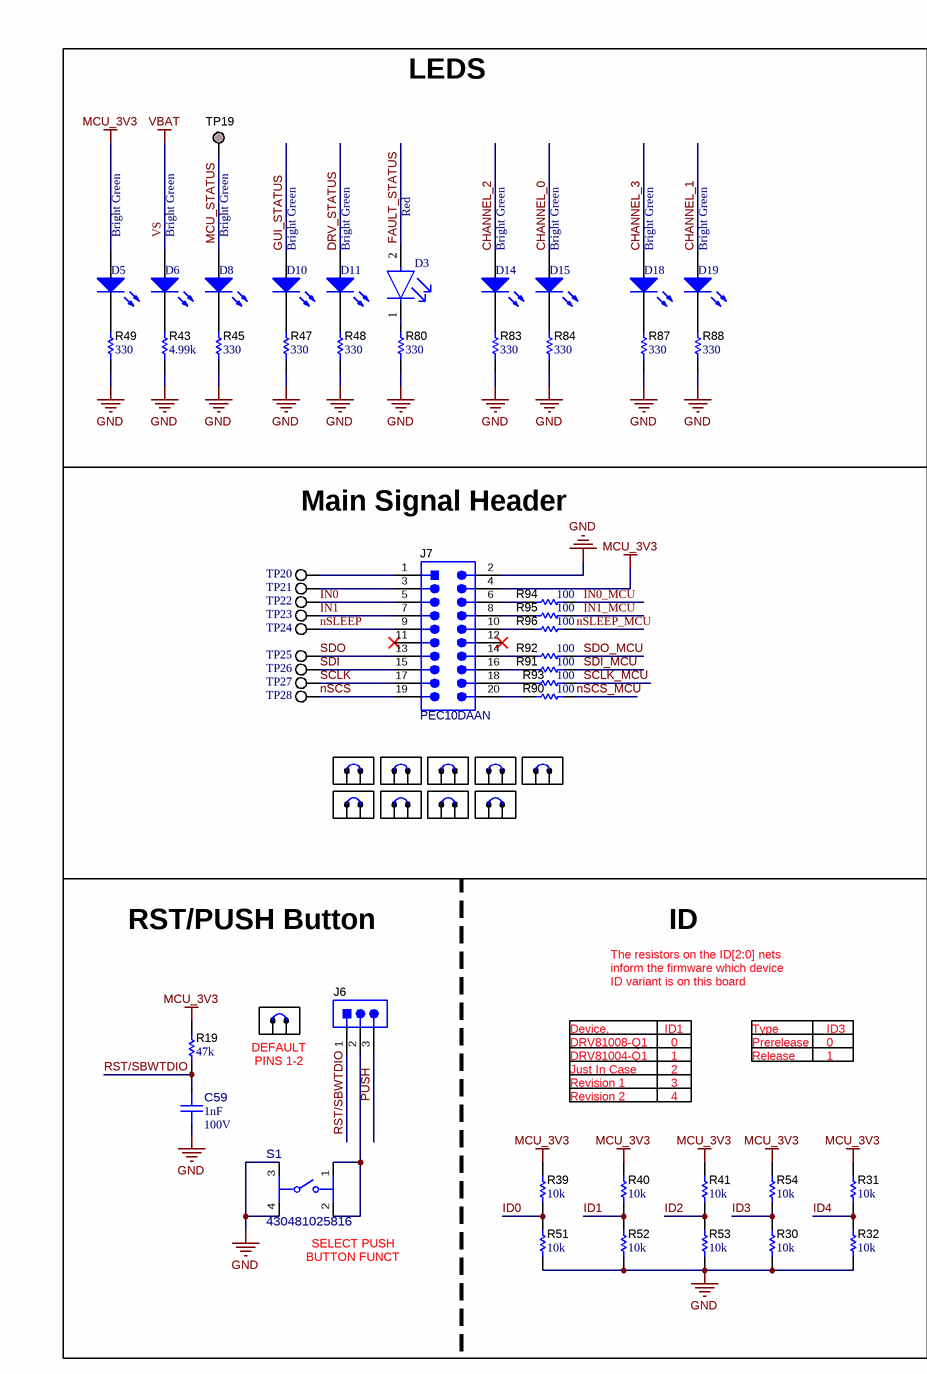
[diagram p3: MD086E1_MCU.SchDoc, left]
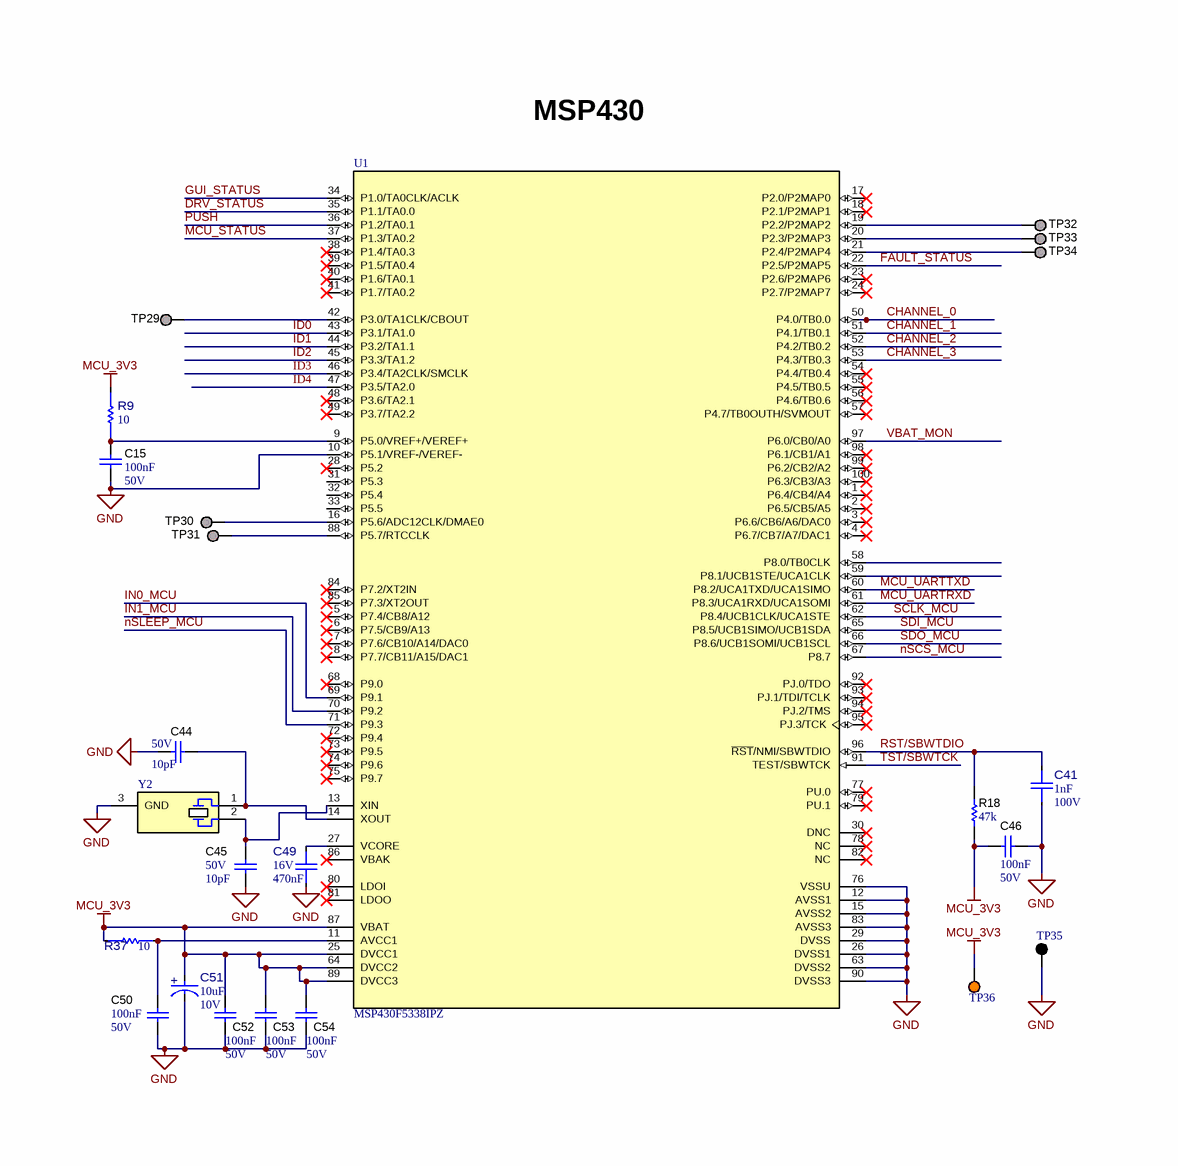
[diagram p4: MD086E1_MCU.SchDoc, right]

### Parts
C15  Cap_F: 100nF  VDC_V: 50V  [0603]  (hidden comment: 885012206095)
C41  ValueDisplayed: 1nF  VDC_V: 100V  [FP-885012006085_0603-MFG]  (hidden comment: 885012006085)
C44  VDC_V: 50V  ValueDisplayed: 10pF  [0402]  (hidden comment: 885012005055)
C45  VDC_V: 50V  ValueDisplayed: 10pF  [0402]  (hidden comment: 885012005055)
C46  Cap_F: 100nF  VDC_V: 50V  [0603]  (hidden comment: 885012206095)
C49  VDC_V: 16V  Cap_F: 470nF  [FP-885012206050_0603-MFG]  (hidden comment: 885012206050)
C50  Cap_F: 100nF  VDC_V: 50V  [0603]  (hidden comment: 885012206095)
C51  ValueDisplayed: 10uF  VDC_V: 10V  [FP-875105240001_SMT_CAP_4MM3_4MM3-MFG]  (hidden comment: 875105240001)
C52  Cap_F: 100nF  VDC_V: 50V  [0603]  (hidden comment: 885012206095)
C53  Cap_F: 100nF  VDC_V: 50V  [0603]  (hidden comment: 885012206095)
C54  Cap_F: 100nF  VDC_V: 50V  [0603]  (hidden comment: 885012206095)
C59  ValueDisplayed: 1nF  VDC_V: 100V  [FP-885012006085_0603-MFG]  (hidden comment: 885012006085)
D3  Color: Red  [FP-150080SS75000-MFG]  (hidden comment: 150080SS75000)
D5  Color: Bright Green  [0805_A]  (hidden comment: 150080VS75000)
D6  Color: Bright Green  [0805_A]  (hidden comment: 150080VS75000)
D8  Color: Bright Green  [0805_A]  (hidden comment: 150080VS75000)
D10  Color: Bright Green  [0805_A]  (hidden comment: 150080VS75000)
D11  Color: Bright Green  [0805_A]  (hidden comment: 150080VS75000)
D14  Color: Bright Green  [0805_A]  (hidden comment: 150080VS75000)
D15  Color: Bright Green  [0805_A]  (hidden comment: 150080VS75000)
D18  Color: Bright Green  [0805_A]  (hidden comment: 150080VS75000)
D19  Color: Bright Green  [0805_A]  (hidden comment: 150080VS75000)
J6  61300311121  [WURTH_61300311121]  (value not drawn)
J7  PEC10DAAN  [SULLINS_PEC10DAAN]
R9  value 10  [FP-560050310009_0402-MFG]  (hidden comment: 560050310009)
R18  ValueDisplayed: 47k  [0402]  (hidden comment: CRCW040247K0JNED)
R19  ValueDisplayed: 47k  [0402]  (hidden comment: CRCW040247K0JNED)
R30  ValueDisplayed: 10k  [0603L]  (hidden comment: RC0603JR-0710KL)
R31  ValueDisplayed: 10k  [0603L]  (hidden comment: RC0603JR-0710KL)
R32  ValueDisplayed: 10k  [0603L]  (hidden comment: RC0603JR-0710KL)
R37  value 10  [FP-560050310009_0402-MFG]  (hidden comment: 560050310009)
R39  ValueDisplayed: 10k  [0603L]  (hidden comment: RC0603JR-0710KL)
R40  ValueDisplayed: 10k  [0603L]  (hidden comment: RC0603JR-0710KL)
R41  ValueDisplayed: 10k  [0603L]  (hidden comment: RC0603JR-0710KL)
R43  ValueDisplayed: 4.99k  [0603L]  (hidden comment: CRCW06034K99FKEAC)
R45  ValueDisplayed: 330  [0603L]  (hidden comment: Resistor)
R47  ValueDisplayed: 330  [0603L]  (hidden comment: Resistor)
R48  ValueDisplayed: 330  [0603L]  (hidden comment: Resistor)
R49  ValueDisplayed: 330  [0603L]  (hidden comment: Resistor)
R51  ValueDisplayed: 10k  [0603L]  (hidden comment: RC0603JR-0710KL)
R52  ValueDisplayed: 10k  [0603L]  (hidden comment: RC0603JR-0710KL)
R53  ValueDisplayed: 10k  [0603L]  (hidden comment: RC0603JR-0710KL)
R54  ValueDisplayed: 10k  [0603L]  (hidden comment: RC0603JR-0710KL)
R80  ValueDisplayed: 330  [0603L]  (hidden comment: Resistor)
R83  ValueDisplayed: 330  [0603L]  (hidden comment: Resistor)
R84  ValueDisplayed: 330  [0603L]  (hidden comment: Resistor)
R87  ValueDisplayed: 330  [0603L]  (hidden comment: Resistor)
R88  ValueDisplayed: 330  [0603L]  (hidden comment: Resistor)
R90  ValueDisplayed: 100  [0402S]  (hidden comment: RC0402FR-07100RL)
R91  ValueDisplayed: 100  [0402S]  (hidden comment: RC0402FR-07100RL)
R92  ValueDisplayed: 100  [0402S]  (hidden comment: RC0402FR-07100RL)
R93  ValueDisplayed: 100  [0402S]  (hidden comment: RC0402FR-07100RL)
R94  value 100  [0402S]  (hidden comment: RC0402FR-07100RL)
R95  ValueDisplayed: 100  [0402S]  (hidden comment: RC0402FR-07100RL)
R96  RC0402FR-07100RL  [0402S]  (value not drawn)
S1  430481025816  [FP-430481025816_SMT_SW_6MM2_6MM2-MFG]
SH-J1  60900213421  [Wurth_60900213421]  (value not drawn)
SH-J6  60900213421  [Wurth_60900213421]  (value not drawn)
SH-J7  60900213421  [Wurth_60900213421]  (value not drawn)
SH-J8  60900213421  [Wurth_60900213421]  (value not drawn)
SH-J9  60900213421  [Wurth_60900213421]  (value not drawn)
SH-J10  60900213421  [Wurth_60900213421]  (value not drawn)
SH-J11  60900213421  [Wurth_60900213421]  (value not drawn)
SH-J12  60900213421  [Wurth_60900213421]  (value not drawn)
SH-J19  60900213421  [Wurth_60900213421]  (value not drawn)
SH-J36  60900213421  [Wurth_60900213421]  (value not drawn)
TP19  TP_H0.45P0.75  [TP_H045P075]  (value not drawn)  (no BOM)
TP20  5002  [Keystone5002]  (value not drawn)
TP21  5002  [Keystone5002]  (value not drawn)
TP22  5002  [Keystone5002]  (value not drawn)
TP23  5002  [Keystone5002]  (value not drawn)
TP24  5002  [Keystone5002]  (value not drawn)
TP25  5002  [Keystone5002]  (value not drawn)
TP26  5002  [Keystone5002]  (value not drawn)
TP27  5002  [Keystone5002]  (value not drawn)
TP28  5002  [Keystone5002]  (value not drawn)
TP29  TP_H0.45P0.75  [TP_H045P075]  (value not drawn)  (no BOM)
TP30  TP_H0.45P0.75  [TP_H045P075]  (value not drawn)  (no BOM)
TP31  TP_H0.45P0.75  [TP_H045P075]  (value not drawn)  (no BOM)
TP32  TP_H0.45P0.75  [TP_H045P075]  (value not drawn)  (no BOM)
TP33  TP_H0.45P0.75  [TP_H045P075]  (value not drawn)  (no BOM)
TP34  TP_H0.45P0.75  [TP_H045P075]  (value not drawn)  (no BOM)
TP35  5011  [Keystone5011]  (value not drawn)
TP36  5003  [Keystone5003]  (value not drawn)
U1  MSP430F5338IPZ  [PZT0100A_N]
Y2  MS3V-T1R 32.768KHZ +/-20PPM 12.5PF  [XTAL_MS3V-T1R]  (value not drawn)

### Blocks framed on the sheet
MSP430: C15 C41 C44-C46 C49-C54 R9 R18 R37 TP29-TP36 U1 Y2

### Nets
GND: C15.2 C41.1 C44.2 C45.2 C46.1 C49.1 C50.2 C51.1(CATHODE) C52.2 C53.2 C54.2 C59.1 J7.2 R30.2 R32.2 R43.1 R45.1 R47.1 R48.1 R49.1 R51.2 R52.2 R53.2 R80.1 R83.1 R84.1 R87.1 R88.1 S1.3 S1.4 TP35.1 U1.10(P5.1/VREF-/VEREF-) U1.12(AVSS1) U1.15(AVSS2) U1.26(DVSS1) U1.29(DVSS) U1.63(DVSS2) U1.76(VSSU) U1.83(AVSS3) U1.90(DVSS3) Y2.3(GND)
MCU_3V3: C46.2 C51.2(ANODE) C52.1 C53.1 C54.1 D5.2(A) J7.4 R9.2 R18.1 R19.2 R31.1 R37.1 R39.1 R40.1 R41.1 R54.1 TP36.1 U1.25(DVCC1) U1.64(DVCC2) U1.87(VBAT) U1.89(DVCC3)
VS: D6.2(A)  [also labelled VBAT]
CHANNEL_0: D15.2(A) U1.50(P4.0/TB0.0)
CHANNEL_1: D19.2(A) U1.51(P4.1/TB0.1)
CHANNEL_2: D14.2(A) U1.52(P4.2/TB0.2)
CHANNEL_3: D18.2(A) U1.53(P4.3/TB0.3)
DRV_STATUS: D11.2(A) U1.35(P1.1/TA0.0)
FAULT_STATUS: D3.2(A) U1.22(P2.5/P2MAP5)
GUI_STATUS: D10.2(A) U1.34(P1.0/TA0CLK/ACLK)
ID0: R39.2 R51.1 U1.43(P3.1/TA1.0)
ID1: R40.2 R52.1 U1.44(P3.2/TA1.1)
ID2: R41.2 R53.1 U1.45(P3.3/TA1.2)
ID3: R30.1 R54.2 U1.46(P3.4/TA2CLK/SMCLK)
ID4: R31.2 R32.1 U1.47(P3.5/TA2.0)
IN0: J7.5 TP22.1
IN0_MCU: R94.1 U1.69(P9.1)
IN1: J7.7 TP23.1
IN1_MCU: R95.1 U1.70(P9.2)
MCU_STATUS: D8.2(A) TP19.1 U1.37(P1.3/TA0.2)
MCU_UARTRXD: U1.61(P8.3/UCA1RXD/UCA1SOMI)
MCU_UARTTXD: U1.60(P8.2/UCA1TXD/UCA1SIMO)
nSCS: J7.19 TP28.1
nSCS_MCU: R90.1 U1.67(P8.7)
nSLEEP: J7.9 TP24.1
nSLEEP_MCU: R96.1 U1.71(P9.3)
PUSH: J6.3 U1.36(P1.2/TA0.1)
RST/SBWTDIO: C41.2 C59.2 J6.1 R18.2 R19.1 U1.96(~{RST}/NMI/SBWTDIO)
SCLK: J7.17 TP27.1
SCLK_MCU: R93.1 U1.62(P8.4/UCB1CLK/UCA1STE)
SDI: J7.15 TP26.1
SDI_MCU: R91.1 U1.65(P8.5/UCB1SIMO/UCB1SDA)
SDO: J7.13 TP25.1
SDO_MCU: R92.1 U1.66(P8.6/UCB1SOMI/UCB1SCL)
TST/SBWTCK: U1.91(TEST/SBWTCK)
VBAT_MON: U1.97(P6.0/CB0/A0)
NetC15_1: C15.1 R9.1 U1.9(P5.0/VREF+/VEREF+)
NetC44_1: C44.1 U1.14(XOUT) Y2.1
NetC45_1: C45.1 U1.13(XIN) Y2.2
NetC49_2: C49.2 U1.27(VCORE)
NetC50_1: C50.1 R37.2 U1.11(AVCC1)
NetD3_1: D3.1(C) R80.2
NetD5_1: D5.1(K) R49.2
NetD6_1: D6.1(K) R43.2
NetD8_1: D8.1(K) R45.2
NetD10_1: D10.1(K) R47.2
NetD11_1: D11.1(K) R48.2
NetD14_1: D14.1(K) R83.2
NetD15_1: D15.1(K) R84.2
NetD18_1: D18.1(K) R87.2
NetD19_1: D19.1(K) R88.2
NetJ6_2: J6.2 S1.1 S1.2
NetJ7_1: J7.1 TP20.1
NetJ7_3: J7.3 TP21.1
NetJ7_6: J7.6 R94.2
NetJ7_8: J7.8 R95.2
NetJ7_10: J7.10 R96.2
NetJ7_14: J7.14 R92.2
NetJ7_16: J7.16 R91.2
NetJ7_18: J7.18 R93.2
NetJ7_20: J7.20 R90.2
NetTP29_1: TP29.1 U1.42(P3.0/TA1CLK/CBOUT)
NetTP30_1: TP30.1 U1.16(P5.6/ADC12CLK/DMAE0)
NetTP31_1: TP31.1 U1.88(P5.7/RTCCLK)
NetTP32_1: TP32.1 U1.19(P2.2/P2MAP2)
NetTP33_1: TP33.1 U1.20(P2.3/P2MAP3)
NetTP34_1: TP34.1 U1.21(P2.4/P2MAP4)

Not connected (* = marked no-connect by the designer): J7 11* 12*; U1 1(P6.4/CB4/A4)* 2(P6.5/CB5/A5)* 3(P6.6/CB6/A6/DAC0)* 4(P6.7/CB7/A7/DAC1)* 5(P7.4/CB8/A12)* 6(P7.5/CB9/A13)* 7(P7.6/CB10/A14/DAC0)* 8(P7.7/CB11/A15/DAC1)* 17(P2.0/P2MAP0)* 18(P2.1/P2MAP1)* 23(P2.6/P2MAP6)* 24(P2.7/P2MAP7)* 28(P5.2)* 30(DNC)* 31(P5.3) 32(P5.4) 33(P5.5) 38(P1.4/TA0.3)* 39(P1.5/TA0.4)* 40(P1.6/TA0.1)* 41(P1.7/TA0.2)* 48(P3.6/TA2.1)* 49(P3.7/TA2.2)* 54(P4.4/TB0.4)* 55(P4.5/TB0.5)* 56(P4.6/TB0.6)* 57(P4.7/TB0OUTH/SVMOUT)* 58(P8.0/TB0CLK) 59(P8.1/UCB1STE/UCA1CLK) 68(P9.0)* 72(P9.4)* 73(P9.5)* 74(P9.6)* 75(P9.7)* 77(PU.0)* 78(NC)* 79(PU.1)* 80(LDOI)* 81(LDOO)* 82(NC)* 84(P7.2/XT2IN)* 85(P7.3/XT2OUT)* 86(VBAK)* 92(PJ.0/TDO)* 93(PJ.1/TDI/TCLK)* 94(PJ.2/TMS)* 95(PJ.3/TCK)* 98(P6.1/CB1/A1)* 99(P6.2/CB2/A2)* 100(P6.3/CB3/A3)*

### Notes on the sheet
- LEDS
- Main Signal Header
- RST/PUSH Button
- ID
- Device.
- The resistors on the ID[2:0] nets inform the firmware which device ID variant is on this board
- ID1
- Type
- ID3
- (near SH-J1) DEFAULT
- PINS 1-2
- DRV81008-Q1
- DRV81004-Q1
- Just In Case
- Revision 1
- Revision 2
- 0
- 1
- 2
- 3
- 4
- Prerelease
- Release
- (near S1) SELECT PUSH
- BUTTON FUNCT

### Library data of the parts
C15 C46 C50 C52-C54 = CMP-0006837-4: as C6 on sheet MD086E1_DRV81xxx
C41 C59 = CMP-0097311-1: as C23 on sheet MD086E1_ezFET
C44 C45 = CMP-0006215-2: as C26 on sheet MD086E1_ezFET
C49 = CMP-0097608-1: as C29 on sheet MD086E1_ezFET
C51 = CMP-0097340-1: as C31 on sheet MD086E1_ezFET
D3 = CMP-1426-00010-2: LED RED CLEAR 0805 SMD; Forward Voltage: 1.9V; Luminous Intensity: 60mcd; Dominant Wavelength: 630nm; Forward Current: 30mA; Viewing Angle: 140°; Lens Color: Colorless; Test Current: 20mA; Lens Size: 1.25mm
D5 D6 D8 D10 D11 D14 D15 D18 D19 = CMP-1426-00009-1: SMD mono-color Chip LED, WL-SMCW, Bright Green; Manufacturer: Wuerth Elektronik
J6 = CMP-0054796-4: Header, 2.54 mm, 3x1, Gold, TH; Manufacturer: Wurth Elektronik; Green_Lifecycle: Active; Green_REACh: Passed; CT: FALSE; CNHeader: TRUE
J7 = CMP-0054623-2: Header, 2.54mm, 10x2, Tin, TH; Manufacturer: Sullins Connector Solutions; Current_A: 3A; Green_Lifecycle: Not Set; Shrouded: N; Gender: Male; Green_REACh: Incomplete; Row_Count: 2; RowSpacing_mm: 2.54; Cert_UL: Y
R9 R37 = CMP-0097401-1: as R64 on sheet MD086E1_ezFET
R18 R19 = CMP-0026935-3: as R57 on sheet MD086E1_ezFET
R30-R32 R39-R41 R51-R54 = CMP-0025886-5: RES, 10 k, 5%, 0.1 W, 0603; Manufacturer: Yageo; Power_W: 100mW; TempCo: 100 ppm/C; Value_Code: 10k0; Value: 10k; EIA_Code: E24; SizeX_mm: 1.6; SizeY_mm: 0.8; SizeZ_mm: 1; Value2: 0.1W; SizeArea_mm2: 1.28; AEC Qualified: N; VDC_V: 75V; AEC Category: Q200; SizeAreaWB_mm2: 4.68
R43 = CMP-0082533-1: RES, 4.99 k, 1%, 0.1 W, 0603; Manufacturer: Vishay-Dale; Value: 4.99k; Value_Code: 4k99; Power_W: 100mW; Value2: 0.1W; VDC_V: 75V; TempCo: 100 ppm/C; EIA_Code: E96; AEC Category: Q200; AEC Qualified: N; SizeAreaWB_mm2: 4.68; SizeX_mm: 1.6; SizeY_mm: 0.8; SizeZ_mm: 1; SizeArea_mm2: 1.28
R45 R47-R49 R80 R83 R84 R87 R88 = CMP-0025785-4: RES, 330, 5%, 0.1 W, AEC-Q200 Grade 0, 0603; PartNumber: CRCW0603330RJNEA; Manufacturer: Vishay-Dale; Value: 330; Value_Code: 330R; Power_W: 100mW; Value2: 0.1W; VDC_V: 75V; TempCo: 200 ppm/C; EIA_Code: E24; AEC Category: Q200; AEC Qualified: Y; AEC Grade: 0; SizeX_mm: 1.6; SizeY_mm: 0.8; SizeZ_mm: 1; SizeArea_mm2: 1.28
R90-R93 R95 R96 = CMP-0026722-1: RES, 100, 1%, 0.063 W, 0402; Manufacturer: Yageo America; Power_W: 63mW; TempCo: 100 ppm/C; Value_Code: 100R; U/M: EA; Value: 100; EIA_Code: E96; SizeX_mm: 1; SizeY_mm: 0.5; SizeZ_mm: 0.6; Value2: 0.063W; AEC Qualified: N; VDC_V: 50V; AEC Category: Q200
R94 = CMP-0026722-1: RES, 100, 1%, 0.063 W, 0402; Manufacturer: Yageo America; Power_W: 63mW; TempCo: 100 ppm/C; Value_Code: 100R; U/M: EA; EIA_Code: E96; SizeX_mm: 1; SizeY_mm: 0.5; SizeZ_mm: 0.6; Value2: 0.063W; AEC Qualified: N; VDC_V: 50V; AEC Category: Q200
S1 = CMP-0097347-1: Tactile Switch SPST-NO Top Actuated Surface Mount; Manufacturer: Wurth Electronics; VDC_V: 12V; Electromechanical Life: 1000000Cycles; SizeZ_mm: 2.7mm; Coil Resistance_ohm: 100mΩ; Operating Force: 160gf; AEC Qualified: No; Contact Current Rating: 50mA
SH-J1 SH-J6-SH-J12 SH-J19 SH-J36 = CMP-0003761-2: as SH-J22 on sheet MD086E1_ezFET
TP19 TP29-TP34 = CMP-0003719-1: Testpoint; Manufacturer: Texas Instruments; CompType: Pad
TP20-TP28 = CMP-0055139-2: Test Point, Miniature, White, TH; Manufacturer: Keystone Electronics; ContactFinish: Silver; Green_REACh: Passed; CT: TRUE; Green_Lifecycle: Active; CNHeader: FALSE
TP35 = CMP-0055148-2: as TP1 on sheet MD086E1_DRV81xxx
TP36 = CMP-0055140-2: Test Point, Miniature, Orange, TH; Manufacturer: Keystone Electronics; CNHeader: FALSE; Green_Lifecycle: Active; Green_REACh: Passed; ContactFinish: Silver; CT: TRUE
U1 = CMP-0038879-1: 20 MHz Mixed Signal Microcontroller with 256 KB Flash, 18432 B SRAM and 74 GPIOs, -40 to 85 degC, 100-pin QFP (PZ), Green (RoHS & no Sb/Br); Manufacturer: Texas Instruments; Flash(KB): 256; USCI_B (I2C & SPI): 2; ADC Channels: 16; Comparators: Yes; Frequency(MHz): 20; DMA: 3; SRAM(B): 18432; Multiplier: 32x32; GPIO: 74; Timers - 16-bit: 4; SubFamily: 5 Series; ADC: 12-bit SAR
Y2 = CMP-0004566-4: Crystal, 32.768 kHz, 12.5pF, SMD; Manufacturer: Micro Crystal AG; TaMin_C: -40°C; TaMax_C: 85°C; AEC Category: Q200; AEC Qualified: N; Frequency Tolerance: 20 ppm

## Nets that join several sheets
GND: MD086E1_DRV81xxx (37 pins), MD086E1_ezFET (45 pins), MD086E1_MCU (41 pins)
MCU_3V3: MD086E1_ezFET (J2.2 J10.10), MD086E1_MCU (21 pins)
VS: MD086E1_DRV81xxx (11 pins), MD086E1_MCU (D6.2)
IN0: MD086E1_DRV81xxx (U5.13), MD086E1_MCU (J7.5 TP22.1)
IN1: MD086E1_DRV81xxx (U5.12), MD086E1_MCU (J7.7 TP23.1)
MCU_UARTRXD: MD086E1_ezFET (J10.8), MD086E1_MCU (U1.61)
MCU_UARTTXD: MD086E1_ezFET (J10.6), MD086E1_MCU (U1.60)
nSCS: MD086E1_DRV81xxx (U5.1), MD086E1_MCU (J7.19 TP28.1)
nSLEEP: MD086E1_DRV81xxx (U5.11), MD086E1_MCU (J7.9 TP24.1)
RST/SBWTDIO: MD086E1_ezFET (J10.4), MD086E1_MCU (6 pins)
SCLK: MD086E1_DRV81xxx (U5.2), MD086E1_MCU (J7.17 TP27.1)
SDI: MD086E1_DRV81xxx (U5.3), MD086E1_MCU (J7.15 TP26.1)
SDO: MD086E1_DRV81xxx (U5.4), MD086E1_MCU (J7.13 TP25.1)
TST/SBWTCK: MD086E1_ezFET (J10.2), MD086E1_MCU (U1.91)
VBAT_MON: MD086E1_DRV81xxx (D20.1 R97.1 R98.2), MD086E1_MCU (U1.97)

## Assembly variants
001: not fitted FID1 FID2 FID3 LBL2 R31 R39 R40 R41 R54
